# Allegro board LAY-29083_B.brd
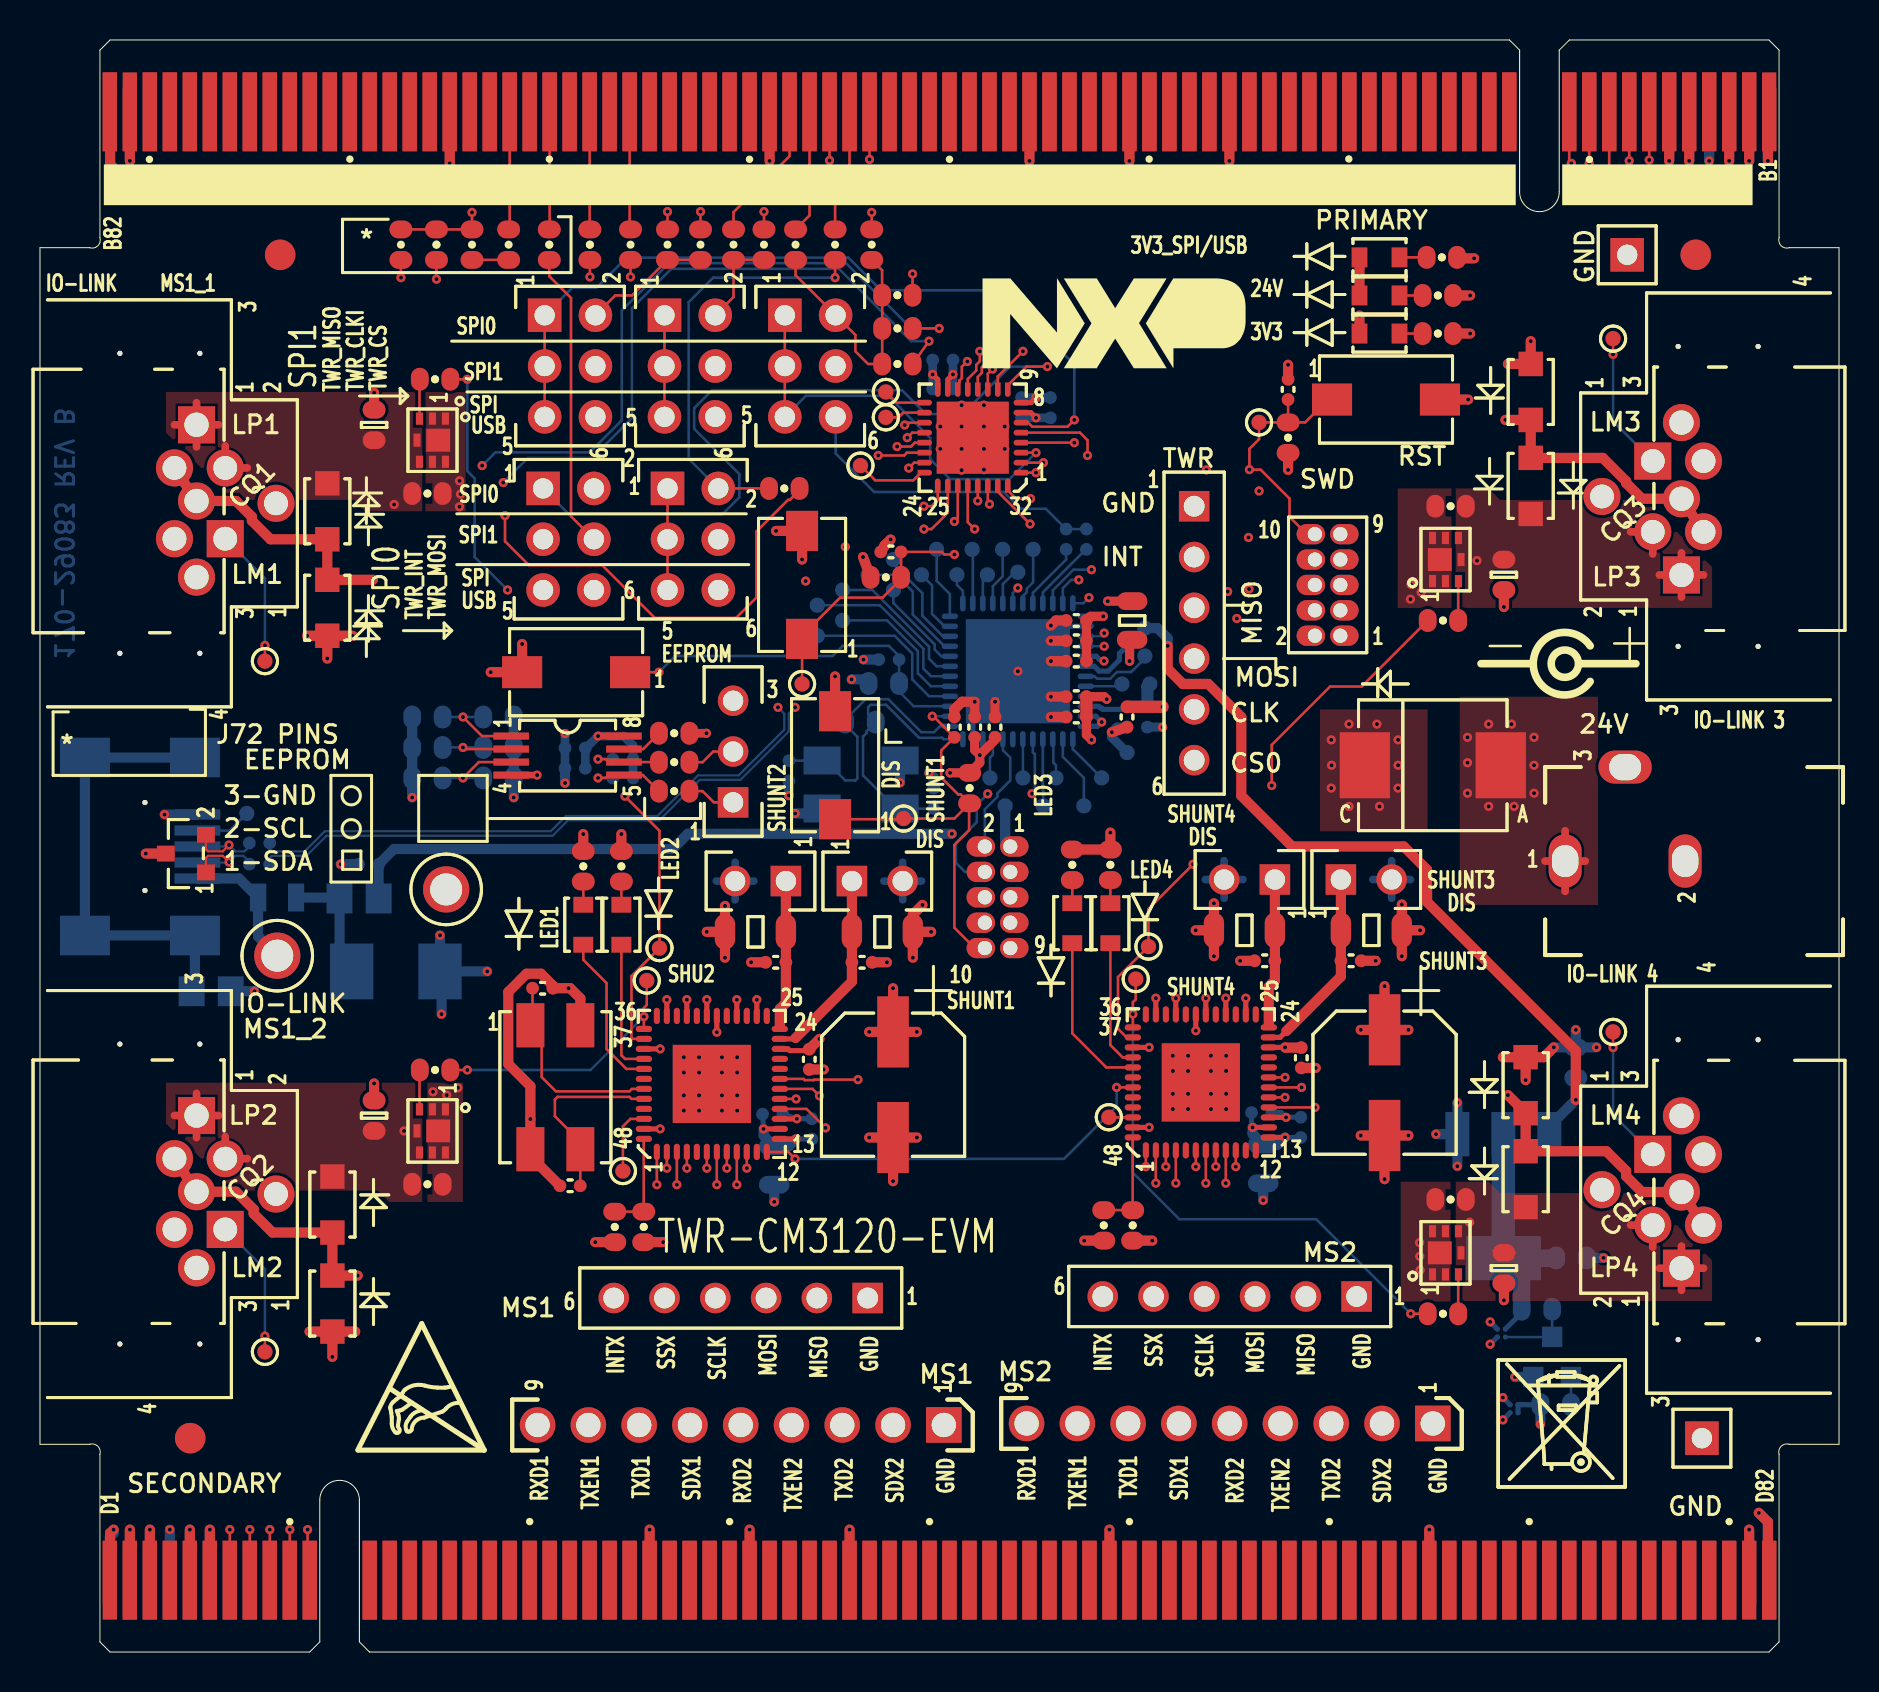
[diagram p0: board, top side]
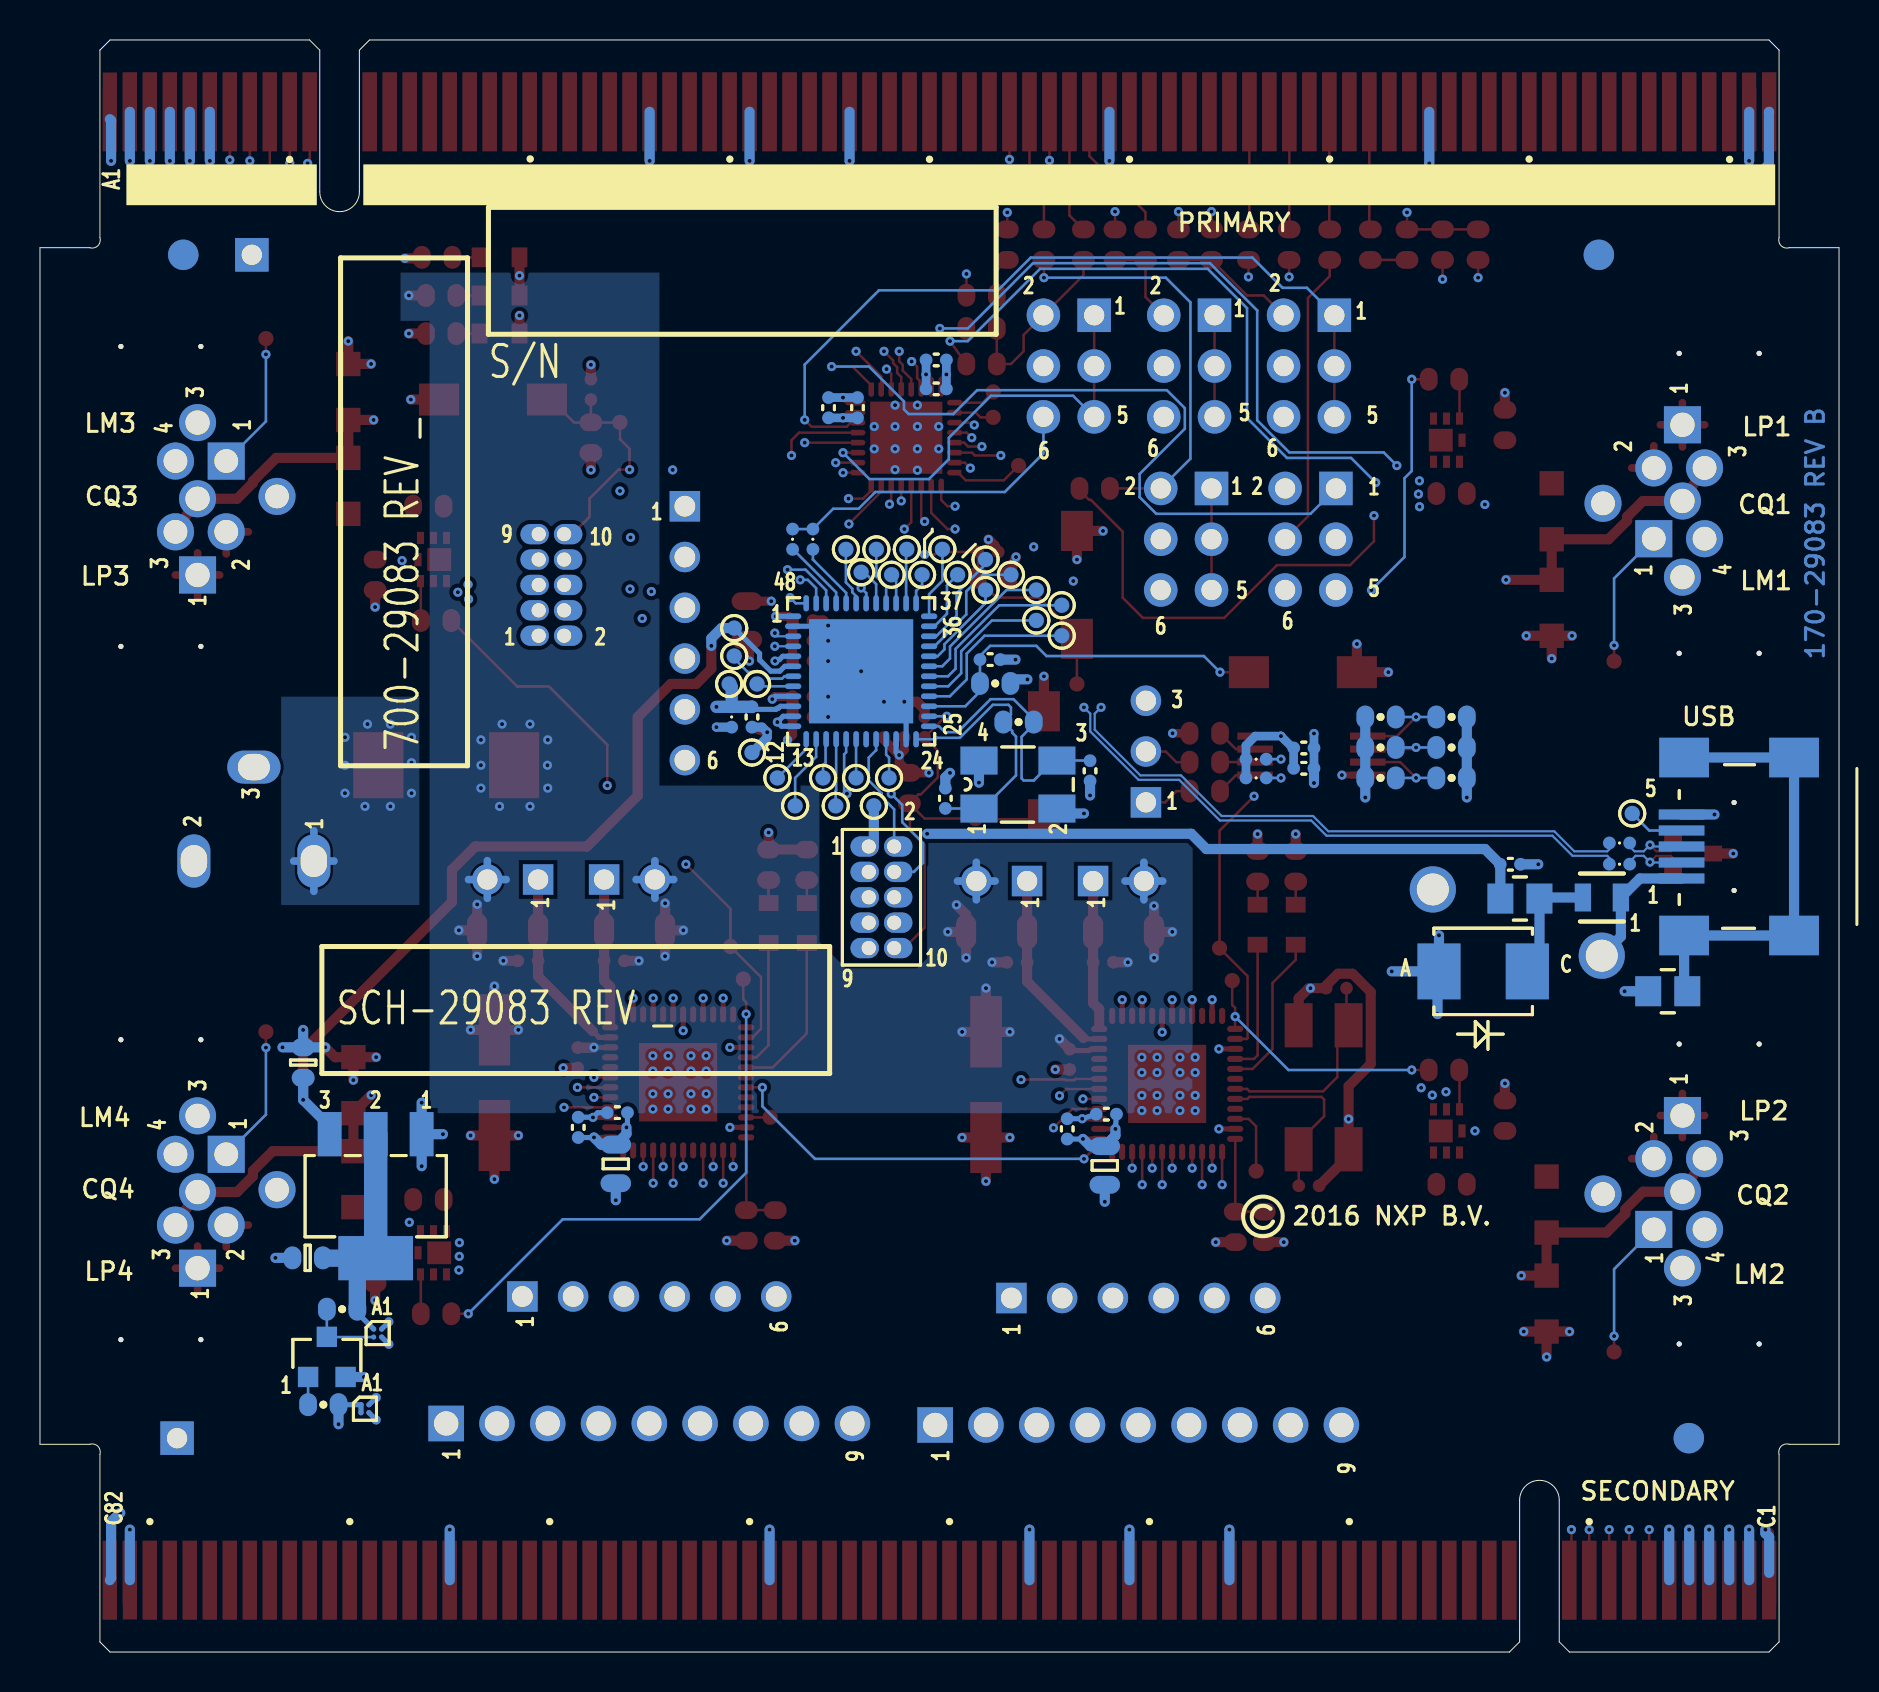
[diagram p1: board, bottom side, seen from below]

Outline 89.99 x 80.62 mm; copper layers: TOP, L2_PWR, L3_INT_1, L4_INT_2, L5_GND, BOTTOM. Coordinates in mm from the lower left corner of the outline.
Outline path: 0,70.23 0,10.39 2.49,10.39 arc(2.9,10.29) 3,9.88 3,0.51 3.51,0 13.49,0 14,0.51 14,7.59 arc(14.99,8.59) 15.98,7.59 15.98,0.51 16.48,0 86.49,0 86.99,0.51 86.99,9.88 arc(87.1,10.29) 87.5,10.39 89.99,10.39 89.99,70.23 87.5,70.23 arc(87.1,70.33) 86.99,70.74 86.99,80.11 86.49,80.62 76.5,80.62 76,80.11 76,73.03 arc(75.01,72.03) 74.02,73.03 74.02,80.11 73.51,80.62 3.51,80.62 3,80.11 3,70.74 arc(2.9,70.33) 2.49,70.23 0,70.23

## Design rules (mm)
net group USB_CONN_DN: nets USB_CONN_DN USB_DM
net group USB_CONN_DP: nets USB_CONN_DP USB_DP
net group POWER: nets 3V3_LDO 5V MS1_CQ1 MS1_CQ2 MS2_CQ1 MS2_CQ2 N52284736 P5V0_USB_CONN_VBUS P5V_USB SHIELD_K20USB VREFH

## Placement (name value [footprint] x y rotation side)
C5  0.1UF  [CC0402_25]  62.43 63.14 90 top
C6  4700PF  [CC0603_OV]  16.71 61.37 90 top
C7  0.1UF  [CC0402_25]  42.57 55.02 180 top
C8  4700PF  [CC0603_OV]  73.23 53.87 270 top
C9  1.0UF  [CC0402_25]  51.84 51.59 180 top
C10  2.2UF  [CC0805_OV]  54.63 51.59 90 top
C11  0.1UF  [CC0402_25]  51.84 50.57 180 top
C12  0.1UF  [CC0402_25]  51.84 49.56 180 top
C13  1.0UF  [CC0402_25]  51.84 47.78 180 top
C14  0.1UF  [CC0402_25]  51.84 46.76 180 top
C15  0.1UF  [CC0402_25]  54.38 46.76 90 top
C16  0.1UF  [CC0402_25]  45.74 46.25 90 top
C17  1.0UF  [CC0402_25]  46.76 46.25 90 top
C18  0.1UF  [CC0402_25]  47.77 46.25 90 top
C19  0.01UF  [CC0402_25]  61.26 34.57 0 top
C20  0.01UF  [CC0402_25]  65.58 34.57 180 top
C21  0.01UF  [CC0402_25]  36.8 34.49 0 top
C22  0.01UF  [CC0402_25]  41.12 34.49 180 top
C23  18PF  [CC0402_25]  25.15 33.2 0 top
C24  0.1uF  [CC0402_25]  63.09 29.72 270 top
C25  0.1uF  [CC0402_25]  38.48 29.64 270 top
C26  47UF  [CASE_D_AL]  67.26 28.47 270 top
C27  47UF  [CASE_D_AL]  42.67 28.37 270 top
C28  4700PF  [CC0603_OV]  16.71 26.82 90 top
C29  18PF  [CC0402_25]  26.52 23.32 180 top
C30  4700PF  [CC0603_OV]  73.23 19.2 270 top
C50  1.0UF  [CC0402_25]  45.16 64.62 180 bottom
C51  0.1UF  [CC0402_25]  45.16 63.17 180 bottom
C52  1.0UF  [CC0402_25]  50.55 62.23 90 bottom
C53  0.1UF  [CC0402_25]  49.1 62.23 90 bottom
C54  0.1UF  [CC0402_25]  42.46 49.63 180 bottom
C55  1.0UF  [CC0402_25]  54.38 46.76 270 bottom
C56  0.1UF  [CC0402_25]  26.77 45.21 180 bottom
C57  1.0UF  [CC0402_25]  26.77 44.2 180 bottom
C58  22PF  [CC0402_25]  37.47 44.07 270 bottom
C59  22PF  [CC0402_25]  44.7 42.7 90 bottom
C60  1.0UF  [CC0402_25]  16.44 39.4 180 bottom
C61  10uF  [CC0603_OV]  76.83 29.48 90 bottom
C65  0.1uF  [CC0402_25]  61.11 26.97 0 bottom
C66  0.1uF  [CC0402_25]  36.65 26.9 0 bottom
C67  0.1uF  [CC0402_25]  63.07 26.24 90 bottom
C68  0.1uF  [CC0402_25]  38.61 26.16 90 bottom
C70  10.0uF  [CC0805_OV]  61.19 24.41 270 bottom
C71  10.0uF  [CC0805_OV]  36.73 24.33 270 bottom
C75  10uF  [CC0603_OV]  76.6 19.71 0 bottom
D5  LED/GRN  [LED2_2P1X1P5_NSP]  67.01 69.75 0 top
D6  LED/GRN  [LED2_2P1X1P5_NSP]  67.01 67.84 0 top
D7  LED/GRN  [LED2_2P1X1P5_NSP]  67.01 65.94 0 top
D8  PTVS33VS1UR  [SOD123W]  74.57 63.02 90 top
D9  PTVS33VS1UR  [SOD123W]  74.57 58.32 90 top
D10  PTVS33VS1UR  [SOD123W]  14.37 57.05 270 top
D11  PTVS33VS1UR  [SOD123W]  14.37 52.22 270 top
D12  B560C-13-F  [SMC_CASE403]  69.67 44.35 0 top
D13  LED/GRN  [LED2_2P1X1P5_NSP]  51.64 36.45 90 top
D14  LED/GRN  [LED2_2P1X1P5_NSP]  53.54 36.45 90 top
D15  LED/GRN  [LED2_2P1X1P5_NSP]  27.18 36.37 90 top
D16  LED/GRN  [LED2_2P1X1P5_NSP]  29.08 36.37 90 top
D17  PTVS33VS1UR  [SOD123W]  74.32 28.35 90 top
D18  PTVS33VS1UR  [SOD123W]  74.32 23.65 90 top
D19  PTVS33VS1UR  [SOD123W]  14.63 22.38 270 top
D20  PTVS33VS1UR  [SOD123W]  14.63 17.43 270 top
D50  1SMB5919BT3G  [CASE403A_03]  17.8 34.04 0 bottom
F50  MFU0805FF00500P100  [FUSE_2X1P4]  11.86 37.73 0 bottom
J5  PCI EXPRESS TOWER SYSTEM  [CN2X82_FINGER_ASS]  3 14.76 0 top
J6  HDR 2X3  [HDR203]  25.24 66.85 0 top
J7  HDR 2X3  [HDR203]  31.24 66.85 0 top
J8  HDR 2X3  [HDR203]  37.26 66.85 0 top
J9  1436686  [CON5_TH_1436686]  80.67 59.56 90 top
J10  PLUG_1X3  [CON1X3_3P81_9P2X12P82]  82.11 53.87 90 top
J11  PLUG_1X3  [CON1X3_3P81_9P2X12P82]  7.83 61.37 270 top
J12  1436686  [CON5_TH_1436686]  9.27 55.68 270 top
J13  HDR 2X3  [HDR203]  25.17 58.19 0 top
J14  HDR 2X3  [HDR203]  31.39 58.19 0 top
J15  HDR 2X5  [HDR_5X2_FTSH_TH]  65.05 50.83 180 top
J16  HDR_1X3  [HDR103]  34.67 42.49 180 top
J17  CON_1_PWR  [PJ-102AH]  76.29 39.56 0 top
J18  HDR 1X2  [HDR102]  61.77 38.63 270 top
J19  HDR 1X2  [HDR102]  65.07 38.63 90 top
J20  HDR 1X2  [HDR102]  37.31 38.56 270 top
J21  HDR 1X2  [HDR102]  40.61 38.56 90 top
J22  1436686  [CON5_TH_1436686]  80.67 24.89 90 top
J23  PLUG_1X3  [CON1X3_3P81_9P2X12P82]  7.83 26.83 270 top
J24  PLUG_1X3  [CON1X3_3P81_9P2X12P82]  82.11 19.19 90 top
J25  1436686  [CON5_TH_1436686]  9.27 21.13 270 top
J52  CONN USB MINI-B  [CON5_USB_RA_SMT]  4.23 40.28 0 bottom
J53  HDR 2X5  [HDR_5X2_FTSH_TH]  48.54 40.29 180 bottom
JP5  HDR 1X1  [HDR101]  79.4 69.88 0 top
JP6  HDR 1X6  [HDR106_TH_TSW]  57.73 57.3 0 top
JP7  HDR 1X6  [HDR106_TH_TSW]  65.86 17.78 270 top
JP8  HDR 1X6  [HDR106_TH_TSW]  41.4 17.7 270 top
JP9  HDR 1X9  [HDR109]  69.67 11.43 270 top
JP10  HDR 1X9  [HDR109]  45.21 11.35 270 top
JP11  HDR 1X1  [HDR101]  83.13 10.69 0 top
L50  330 OHM  [IND_0805]  15.96 37.68 0 bottom
L51  330 OHM  [IND_0805]  8.57 33.05 0 bottom
NOREF  -  []  80.91 51.27 90 top
NOREF#2  -  []  19.63 24.98 90 top
NOREF#3  -  []  50.62 130.33 0 top
NOREF#4  -  []  3.51 0 90 top
NOREF#5  -  []  71.36 53.59 90 top
NOREF#6  -  []  18.98 24.98 0 top
NOREF#7  -  []  0 10.39 90 top
NOREF#8  -  []  69.26 55.69 0 top
NOREF#9  -  []  0 69.57 0 top
NOREF#10  -  []  -12.3 82.45 90 top
NOREF#11  -  []  70.02 19.96 90 top
NOREF#12  -  []  75.52 61.62 90 top
NOREF#13  -  []  69.66 21.04 0 top
NOREF#14  -  []  14.99 7.59 0 top
NOREF#15  -  []  6.73 59.22 90 top
NOREF#16  -  []  71.36 18.91 90 top
NOREF#17  -  []  80.54 47.79 90 top
NOREF#18  -  []  11.81 57.45 90 top
NOREF#19  -  []  4 49.95 90 top
NOREF#20  -  []  -9 52.9 90 top
NOREF#21  -  []  73.37 29.75 0 top
NOREF#22  -  [unnamed#2]  7.51 10.69 0 top
NOREF#23  -  []  13.42 50.82 90 top
NOREF#24  -  []  80.91 16.59 90 top
NOREF#25  -  []  -378.64 230.02 0 top
NOREF#26  -  []  13.42 55.65 0 top
NOREF#27  -  []  85.94 65.29 90 top
NOREF#28  -  []  77.24 28.12 90 top
NOREF#29  -  []  19.63 24.98 90 top
NOREF#30  -  []  18.86 60.6 0 top
NOREF#31  -  []  9.27 24.67 90 top
NOREF#32  -  []  82.11 19.19 90 top
NOREF#33  -  []  72.9 15.75 0 top
NOREF#34  -  []  8 15.4 90 top
NOREF#35  -  []  9.03 51.15 90 top
NOREF#36  -  []  81.94 50.29 90 top
NOREF#37  -  []  19.63 59.52 90 top
NOREF#38  -  []  8 49.95 90 top
NOREF#39  -  []  0 10.39 90 top
NOREF#40  -  []  9.27 55.68 90 top
NOREF#41  -  []  13.68 20.98 90 top
NOREF#42  -  []  19.63 59.52 90 top
NOREF#43  -  []  47.16 64.2 0 top
NOREF#44  -  []  80.54 67.79 90 top
NOREF#45  -  []  73.62 64.42 0 top
NOREF#46  -  []  73.34 11.77 0 top
NOREF#47  -  []  66.01 65.94 0 top
NOREF#48  -  []  66.01 67.84 0 top
NOREF#49  -  []  72.94 8.26 0 top
NOREF#50  -  []  70.02 54.64 90 top
NOREF#51  -  []  -4.3 -37.44 0 top
NOREF#52  -  []  2.22 15.54 0 top
NOREF#53  -  []  69.26 21.01 0 top
NOREF#54  -  []  18.58 25.01 0 top
NOREF#55  -  []  13.68 16.03 0 top
NOREF#56  -  []  71.08 19.96 90 top
NOREF#57  -  []  4 15.4 90 top
NOREF#58  -  []  89.74 11.12 90 top
NOREF#59  -  []  18.98 59.52 0 top
NOREF#60  -  []  73.62 59.72 0 top
NOREF#61  -  []  86.99 80.11 0 top
NOREF#62  -  []  8.33 27.97 0 top
NOREF#63  -  []  -9 32.9 90 top
NOREF#64  -  []  73.34 11.77 90 top
NOREF#65  -  []  73.37 25.05 0 top
NOREF#66  -  []  3 14.76 0 top
NOREF#67  -  []  70.96 18.88 90 top
NOREF#68  -  []  21.91 38.14 0 top
NOREF#69  -  []  89.74 11.12 90 top
NOREF#70  -  []  69.66 21.04 0 top
NOREF#71  -  []  203.02 -79.86 0 top
NOREF#72  -  []  -9 67.45 90 top
NOREF#73  -  []  89.74 45.79 90 top
NOREF#74  -  []  8 49.95 90 top
NOREF#75  -  []  82.11 53.87 90 top
NOREF#76  -  []  77.24 62.79 90 top
NOREF#77  -  []  18.58 25.01 90 top
NOREF#78  -  []  9.27 21.13 90 top
NOREF#79  -  []  29.08 35.37 90 top
NOREF#80  -  []  81.94 15.62 90 top
NOREF#81  -  [unnamed#2]  82.83 69.88 0 top
NOREF#82  -  []  7.83 57.56 90 top
NOREF#83  -  []  66.01 69.75 0 top
NOREF#84  -  []  89.74 11.12 90 top
NOREF#85  -  []  89.74 45.79 90 top
NOREF#86  -  []  75.01 88.58 0 top
NOREF#87  -  []  51.64 35.45 90 top
NOREF#88  -  []  70.96 53.56 90 top
NOREF#89  -  []  13.68 16.03 90 top
NOREF#90  -  []  69.66 55.71 0 top
NOREF#91  -  []  13.42 55.65 90 top
NOREF#92  -  []  70.96 18.88 0 top
NOREF#93  -  []  -9 87.45 90 top
NOREF#94  -  []  89.99 70.23 90 top
NOREF#95  -  []  51.81 -0.01 0 top
NOREF#96  -  []  89.99 11.05 90 top
NOREF#97  -  []  13.46 34.82 0 top
NOREF#98  -  []  75.27 22.25 90 top
NOREF#99  -  []  11.81 22.9 90 top
NOREF#100  -  []  81.94 30.62 90 top
NOREF#101  -  []  75.27 26.95 90 top
NOREF#102  -  []  77.24 28.12 90 top
NOREF#103  -  []  80.54 33.12 90 top
NOREF#104  -  []  80.54 13.12 90 top
NOREF#105  -  []  71.08 54.64 90 top
NOREF#106  -  []  8 15.4 90 top
NOREF#107  -  []  80.67 56.02 90 top
NOREF#108  -  []  3 0.51 0 top
NOREF#109  -  []  19.63 59.52 0 top
NOREF#110  -  []  -12.3 47.9 90 top
NOREF#111  -  []  -12.3 82.45 90 top
NOREF#112  -  []  15.92 10.1 0 top
NOREF#113  -  []  -12.3 47.9 90 top
NOREF#114  -  []  -93.52 -190.35 0 top
NOREF#115  -  []  9.03 16.61 90 top
NOREF#116  -  []  18.58 59.55 0 top
NOREF#117  -  []  77.24 18.12 90 top
NOREF#118  -  []  85.94 30.62 90 top
NOREF#119  -  []  3 14.76 0 top
NOREF#120  -  []  89.74 45.79 90 top
NOREF#121  -  []  13.42 50.82 0 top
NOREF#122  -  []  -88.44 146.2 0 top
NOREF#123  -  []  75.52 56.92 90 top
NOREF#124  -  []  -12.3 72.45 90 top
NOREF#125  -  []  69.66 55.71 0 top
NOREF#126  -  []  13.68 20.98 0 top
NOREF#127  -  []  6.73 24.67 90 top
NOREF#128  -  []  35.05 80.63 0 top
NOREF#129  -  []  73.54 11.97 90 top
NOREF#130  -  []  18.58 59.55 90 top
NOREF#131  -  []  19.63 24.98 0 top
NOREF#132  -  []  9.27 59.22 90 top
NOREF#133  -  []  89.99 10.39 90 top
NOREF#134  -  []  72.7 15.55 0 top
NOREF#135  -  []  18.98 24.98 90 top
NOREF#136  -  []  53.54 35.45 90 top
NOREF#137  -  []  70.96 53.56 0 top
NOREF#138  -  []  77.24 62.79 90 top
NOREF#139  -  []  18.98 59.52 90 top
NOREF#140  -  [unnamed#2]  12.01 69.88 0 top
NOREF#141  -  []  81.94 65.29 90 top
NOREF#142  -  []  0 10.39 90 top
NOREF#143  -  []  -409.17 -284.96 0 top
NOREF#144  -  []  77.24 52.79 90 top
NOREF#145  -  []  73.54 11.97 0 top
NOREF#146  -  []  18.86 26.06 0 top
NOREF#147  -  []  7.83 23.02 90 top
NOREF#148  -  []  27.18 35.37 90 top
NOREF#149  -  []  -12.3 37.9 90 top
NOREF#150  -  []  80.67 21.35 90 top
NOREF#151  -  []  141.19 79.22 0 top
NOREF#152  -  []  72.9 15.75 90 top
NOREF#153  -  []  72.7 15.55 90 top
NOREF#154  -  []  68.61 44.32 90 bottom
NOREF#155  -  []  30.88 22.38 180 bottom
NOREF#156  -  [unnamed#2]  7.51 10.69 180 bottom
NOREF#157  -  []  28.82 21.76 180 bottom
NOREF#158  -  []  42.16 72.25 0 bottom
NOREF#159  -  [unnamed#2]  82.83 69.88 180 bottom
NOREF#160  -  [unnamed#2]  12.01 69.88 180 bottom
NOREF#161  -  []  75.89 28.93 180 bottom
Q5  PMPB85ENEAX  [SOT1220]  19.63 60.6 270 top
Q6  PMPB85ENEAX  [SOT1220]  70.31 54.64 90 top
Q7  PMPB85ENEAX  [SOT1220]  19.63 26.06 270 top
Q8  PMPB85ENEAX  [SOT1220]  70.31 19.96 90 top
Q50  BC847C  [SOT23-40X40]  75.64 14.76 180 bottom
R5  0  [RC0603_OV]  18.06 70.38 270 top
R6  0  [RC0603_OV]  19.83 70.38 270 top
R7  0  [RC0603_OV]  21.61 70.38 270 top
R8  0  [RC0603_OV]  23.44 70.38 90 top
R9  0  [RC0603_OV]  25.48 70.38 90 top
R10  0  [RC0603_OV]  27.51 70.38 90 top
R11  0  [RC0603_OV]  29.54 70.38 90 top
R12  0  [RC0603_OV]  31.39 70.38 90 top
R13  0  [RC0603_OV]  33.04 70.38 90 top
R14  0  [RC0603_OV]  34.69 70.38 90 top
R15  0  [RC0603_OV]  36.22 70.38 90 top
R16  0  [RC0603_OV]  37.8 70.38 90 top
R17  0  [RC0603_OV]  39.77 70.38 90 top
R18  0  [RC0603_OV]  41.61 70.38 90 top
R19  560  [RC0603_OV]  70.13 69.75 0 top
R20  0  [RC0603_OV]  42.89 67.86 0 top
R21  3.83K  [RC0603_OV]  69.93 67.84 180 top
R22  0  [RC0603_OV]  42.89 66.19 0 top
R23  560  [RC0603_OV]  69.93 65.94 0 top
R24  0  [RC0603_OV]  42.89 64.42 0 top
R25  0  [RC0603_OV]  19.76 63.65 0 top
R26  10K  [RC0603_OV]  62.43 60.73 90 top
R27  0  [RC0603_OV]  37.23 58.19 0 top
R28  0  [RC0603_OV]  19.38 57.94 0 top
R29  0  [RC0603_OV]  70.56 57.3 180 top
R30  10K  [RC0603_OV]  42.31 53.75 0 top
R31  0  [RC0603_OV]  70.18 51.59 180 top
R32  0  [RC0603_OV]  31.72 45.95 0 top
R33  0  [RC0603_OV]  31.72 44.5 0 top
R34  10K  [RC0603_OV]  46.5 43.21 270 top
R35  0  [RC0603_OV]  31.72 43.05 0 top
R36  560  [RC0603_OV]  51.64 39.37 90 top
R37  560  [RC0603_OV]  53.54 39.37 90 top
R38  560  [RC0603_OV]  27.18 39.29 90 top
R39  560  [RC0603_OV]  29.08 39.29 90 top
R40  0.5  [RC1206_OV]  60.25 36.09 0 top
R41  0.5  [RC1206_OV]  66.6 36.09 180 top
R42  0.5  [RC1206_OV]  35.79 36.02 0 top
R43  0.5  [RC1206_OV]  42.14 36.02 180 top
R44  0  [RC0603_OV]  19.76 29.11 0 top
R45  0  [RC0603_OV]  19.38 23.39 0 top
R46  0  [RC0603_OV]  70.56 22.63 180 top
R47  0  [RC0603_OV]  53.21 21.34 90 top
R48  0  [RC0603_OV]  54.66 21.34 270 top
R49  0  [RC0603_OV]  28.75 21.26 90 top
R50  0  [RC0402_25]  52.35 55.65 90 bottom
R51  0  [RC0402_25]  51.33 55.65 90 bottom
R52  10K  [RC0603_OV]  42.21 48.44 0 bottom
R53  0  [RC0402_25]  55.39 46.76 270 bottom
R54  2.2K  [RC0603_OV]  22.94 46.76 0 bottom
R55  2.2K  [RC0603_OV]  19.38 46.76 0 bottom
R56  1.0M  [RC0603_OV]  41.04 46.51 180 bottom
R57  2.2K  [RC0603_OV]  22.94 45.24 0 bottom
R58  2.2K  [RC0603_OV]  19.38 45.24 0 bottom
R59  2.2K  [RC0402_25]  29.16 44.65 180 bottom
R60  2.2K  [RC0402_25]  29.16 43.71 180 bottom
R61  2.2K  [RC0603_OV]  22.94 43.71 0 bottom
R62  2.2K  [RC0603_OV]  19.38 43.71 0 bottom
R63  33  [RC0402_25]  10.98 40.46 0 bottom
R64  33  [RC0402_25]  10.98 39.4 0 bottom
R65  3.3K  [RC0603_OV]  74.88 17.14 0 bottom
R66  33.0K  [RC0603_OV]  75.82 12.37 0 bottom
R67  0  [RC0603_OV]  30.2 21.26 270 top
R68  0  [RC0603_OV]  70.18 16.92 180 top
SW5  EVQ-PE105K  [SW2_SPST_3P5X6P0_5P0]  67.33 62.64 270 top
SW6  EVQ-PE105K  [SW2_SPST_3P5X6P0_5P0]  38.12 53.37 0 top
SW7  EVQ-PE105K  [SW2_SPST_3P5X6P0_5P0]  26.82 49 90 top
SW8  EVQ-PE105K  [SW2_SPST_3P5X6P0_5P0]  39.77 44.35 0 top
TP5  -  [TPAD_030]  78.69 65.68 90 top
TP6  -  [TPAD_030]  42.31 63.02 0 top
TP7  -  [TPAD_030]  42.31 61.75 0 top
TP8  -  [TPAD_030]  60.98 61.49 180 top
TP9  -  [TPAD_030]  41.04 59.34 0 top
TP10  -  [TPAD_030]  11.25 49.56 270 top
TP11  -  [TPAD_030]  38.12 48.41 0 top
TP12  -  [TPAD_030]  43.2 41.68 0 top
TP13  TESTLOOP_BLACK  [TP_TH_063]  20.32 38.14 0 top
TP14  -  [TPAD_030]  55.45 35.28 90 top
TP15  -  [TPAD_030]  30.99 35.2 90 top
TP16  TESTLOOP_RED  [TP_TH_063]  11.87 34.82 0 top
TP17  -  [TPAD_030]  54.81 33.66 90 top
TP18  -  [TPAD_030]  30.35 33.58 90 top
TP19  -  [TPAD_030]  78.69 31.01 90 top
TP20  -  [TPAD_030]  53.47 26.75 90 top
TP21  -  [TPAD_030]  29.16 24.05 90 top
TP22  -  [TPAD_030]  11.25 15.01 270 top
TP57  -  [TPAD_030]  49.68 55.14 180 bottom
TP58  -  [TPAD_030]  48.15 55.14 180 bottom
TP64  -  [TPAD_030]  46.63 55.14 180 bottom
TP66  -  [TPAD_030]  44.85 55.14 180 bottom
TP67  -  [TPAD_030]  42.69 54.64 180 bottom
TP68  -  [TPAD_030]  48.92 54 180 bottom
TP69  -  [TPAD_030]  47.39 53.87 180 bottom
TP70  -  [TPAD_030]  45.87 53.87 180 bottom
TP71  -  [TPAD_030]  44.09 53.87 180 bottom
TP72  -  [TPAD_030]  41.42 53.87 180 bottom
TP73  -  [TPAD_030]  42.69 53.11 180 bottom
TP74  -  [TPAD_030]  40.15 53.11 180 bottom
TP75  -  [TPAD_030]  38.88 52.35 180 bottom
TP76  -  [TPAD_030]  40.15 51.59 180 bottom
TP77  -  [TPAD_030]  55.27 51.21 180 bottom
TP78  -  [TPAD_030]  38.88 50.83 180 bottom
TP79  -  [TPAD_030]  55.27 49.81 180 bottom
TP80  -  [TPAD_030]  55.52 48.41 180 bottom
TP81  -  [TPAD_030]  54.12 48.41 180 bottom
TP82  -  [TPAD_030]  54.38 44.98 180 bottom
TP83  -  [TPAD_030]  53.11 43.71 180 bottom
TP84  -  [TPAD_030]  50.82 43.71 180 bottom
TP85  -  [TPAD_030]  49.17 43.71 180 bottom
TP86  -  [TPAD_030]  47.52 43.71 180 bottom
TP87  -  [TPAD_030]  52.22 42.32 180 bottom
TP88  -  [TPAD_030]  50.19 42.32 180 bottom
TP89  -  [TPAD_030]  48.28 42.32 180 bottom
TP90  -  [TPAD_030]  10.34 41.94 180 bottom
U5  MKL17Z64VFM4  [QFN32_S142EP]  46.66 60.73 180 top
U6  24FC256  [TSSOP8]  26.39 44.83 0 top
U7  GSOT05C-GS08  [SOT23_A]  7.3 39.93 90 top
U8  MC34CM3120EP  [QFN48_0P5_7X7_EP3P9_NSP]  58.07 28.49 90 top
U9  MC34CM3120EP  [QFN48_0P5_7X7_EP3P9_NSP]  33.61 28.41 90 top
U50  MKL25Z128VFT4  [QFN_48_0P5_7X7]  48.92 49.05 180 bottom
U51  NCP1117ST33T3G  [SOT223]  73.2 22.8 0 bottom
U52  NX3P190UK  [WLCSP4_0P4_0P8X0P8_SMDP]  73.1 15.95 180 bottom
U53  NX3P190UK  [WLCSP4_0P4_0P8X0P8_SMDP]  73.74 12.17 180 bottom
Y5  14.7456MHZ  [XTAL_4_7X5]  25.78 28.24 270 top
Y50  8MHZ  [XTLOSC4_5X3MM_SM]  41.07 43.38 180 bottom

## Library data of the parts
C5-C9 C11-C25 C28-C30 C50-C61 C65-C68 C70 C71 C75 = CAP_NP
C10 = CAP_NP: tolerance: 10%
C26 C27 = CAP_POL
D5-D7 D13-D16 = LED
D8-D11 D17-D20 = DIODE_TVS
D12 = DIODE_SCHTKY
D50 = ZDIODE
F50 = FUSE
J5 = CONN_PCI_XPRESS_X16_328P
J6-J8 J13 J14 = CONN_HDR_3X2
J9 J12 J22 J25 = CON5_DIN
J10 J11 J16 J23 J24 = CONN_HDR_3X1
J15 J53 = CONN_HDR_5X2
J17 = DC POWER JACK
J18-J21 = CONN_HDR_2X1
J52 = USB_MINI_AB_RECEPTACLE
JP5 JP11 = CONN_HDR_1X1
JP6-JP8 = CONN_HDR_6X1
JP9 JP10 = CONN_HDR_9X1
L50 L51 = BEAD: tolerance: 25%
Q5-Q8 = PMPB85ENEA_SOT1220_8P
Q50 = NPN
R5-R18 R20-R22 R24-R35 R40-R62 R65-R68 = RES
R19 R23 R36-R39 = RES: tolerance: 5%
R63 R64 = RES: signal model: RES_RC0402_25_DISCRETE_0.4MM__1_33
SW5-SW8 = SW2P
TP5-TP12 TP14 TP15 TP17-TP22 TP57 TP58 TP64 TP66-TP90 = TESTLOOP
TP13 TP16 = TestLoop
U5 = KL17Z64VF_QFN_32P_EP
U6 = Atmel_Serial_EEPROM_64K-1
U7 = DIODE_2LINE_ESD
U8 U9 = MC34CM3120_48P
U50 = MKL25Z128VFT4_49P
U51 = LD1117AS18
U52 U53 = ADP172_CSP_4P
Y5 = XTAL_13Y
Y50 = CRYSTAL_JXS63

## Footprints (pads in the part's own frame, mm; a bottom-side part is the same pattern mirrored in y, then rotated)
CASE403A_03
  rect 2.159x2.794 smd: A(2.21,0) C(-2.21,0)
CASE_D_AL
  rect 3.556x1.575 smd: 1(-2.642,0) 2(2.642,0)
CC0402_25
  round 0.635 smd: 1(-0.508,0) 2(0.508,0)
CC0603_OV
  oval 0.889x1.143 smd: 1(-0.762,0) 2(0.762,0)
CC0805_OV
  oval 0.889x1.524 smd: 1(-0.965,0) 2(0.965,0)
CN2X82_FINGER_ASS
  rect 0.711x3.2 smd: A1(83.499,61.9) B81(1.499,61.9) C1(0.499,-10.795) D81(82.499,-10.795)
  rect 0.711x3.937 smd: A2(82.499,62.268) A3(81.499,62.268) A4(80.499,62.268) A5(79.499,62.268) A6(78.499,62.268) A7(77.499,62.268) A8(76.499,62.268) A9(75.499,62.268) A10(74.499,62.268) A11(73.499,62.268) A12(70.499,62.268) A13(69.499,62.268) A14(68.499,62.268) A15(67.499,62.268) A16(66.499,62.268) A17(65.499,62.268) A18(64.499,62.268) A19(63.499,62.268) A20(62.499,62.268) A21(61.499,62.268) A22(60.499,62.268) A23(59.499,62.268) A24(58.499,62.268) A25(57.499,62.268) A26(56.499,62.268) A27(55.499,62.268) A28(54.499,62.268) A29(53.499,62.268) A30(52.499,62.268) A31(51.499,62.268) A32(50.499,62.268) A33(49.499,62.268) A34(48.499,62.268) A35(47.499,62.268) A36(46.499,62.268) A37(45.499,62.268) A38(44.499,62.268) A39(43.499,62.268) A40(42.499,62.268) A41(41.499,62.268) A42(40.499,62.268) A43(39.499,62.268) A44(38.499,62.268) A45(37.499,62.268) A46(36.499,62.268) A47(35.499,62.268) A48(34.499,62.268) A49(33.499,62.268) A50(32.499,62.268) A51(31.499,62.268) A52(30.499,62.268) A53(29.499,62.268) A54(28.499,62.268) A55(27.499,62.268) A56(26.499,62.268) A57(25.499,62.268) A58(24.499,62.268) A59(23.499,62.268) A60(22.499,62.268) A61(21.499,62.268) A62(20.499,62.268) A63(19.499,62.268) A64(18.499,62.268) A65(17.499,62.268) A66(16.499,62.268) A67(15.499,62.268) A68(14.499,62.268) A69(13.499,62.268) A70(12.499,62.268) A71(11.499,62.268) A72(10.499,62.268) A73(9.499,62.268) A74(8.499,62.268) A75(7.499,62.268) A76(6.499,62.268) A77(5.499,62.268) A78(4.499,62.268) A79(3.499,62.268) A80(2.499,62.268) A81(1.499,62.268) A82(0.499,62.268) B1(83.499,62.268) B2(82.499,62.268) B3(81.499,62.268) B4(80.499,62.268) B5(79.499,62.268) B6(78.499,62.268) B7(77.499,62.268) B8(76.499,62.268) B9(75.499,62.268) B10(74.499,62.268) B11(73.499,62.268) B12(70.499,62.268) B13(69.499,62.268) B14(68.499,62.268) B15(67.499,62.268) B16(66.499,62.268) B17(65.499,62.268) B18(64.499,62.268) B19(63.499,62.268) B20(62.499,62.268) B21(61.499,62.268) B22(60.499,62.268) B23(59.499,62.268) B24(58.499,62.268) B25(57.499,62.268) B26(56.499,62.268) B27(55.499,62.268) B28(54.499,62.268) B29(53.499,62.268) B30(52.499,62.268) B31(51.499,62.268) B32(50.499,62.268) B33(49.499,62.268) B34(48.499,62.268) B35(47.499,62.268) B36(46.499,62.268) B37(45.499,62.268) B38(44.499,62.268) B39(43.499,62.268) B40(42.499,62.268) B41(41.499,62.268) B42(40.499,62.268) B43(39.499,62.268) B44(38.499,62.268) B45(37.499,62.268) B46(36.499,62.268) B47(35.499,62.268) B48(34.499,62.268) B49(33.499,62.268) B50(32.499,62.268) B51(31.499,62.268) B52(30.499,62.268) B53(29.499,62.268) B54(28.499,62.268) B55(27.499,62.268) B56(26.499,62.268) B57(25.499,62.268) B58(24.499,62.268) B59(23.499,62.268) B60(22.499,62.268) B61(21.499,62.268) B62(20.499,62.268) B63(19.499,62.268) B64(18.499,62.268) B65(17.499,62.268) B66(16.499,62.268) B67(15.499,62.268) B68(14.499,62.268) B69(13.499,62.268) B70(12.499,62.268) B71(11.499,62.268) B72(10.499,62.268) B73(9.499,62.268) B74(8.499,62.268) B75(7.499,62.268) B76(6.499,62.268) B77(5.499,62.268) B78(4.499,62.268) B79(3.499,62.268) B80(2.499,62.268) B82(0.499,62.268) C2(1.499,-11.163) C3(2.499,-11.163) C4(3.499,-11.163) C5(4.499,-11.163) C6(5.499,-11.163) C7(6.499,-11.163) C8(7.499,-11.163) C9(8.499,-11.163) C10(9.499,-11.163) C11(10.499,-11.163) C12(13.499,-11.163) C13(14.499,-11.163) C14(15.499,-11.163) C15(16.499,-11.163) C16(17.499,-11.163) C17(18.499,-11.163) C18(19.499,-11.163) C19(20.499,-11.163) C20(21.499,-11.163) C21(22.499,-11.163) C22(23.499,-11.163) C23(24.499,-11.163) C24(25.499,-11.163) C25(26.499,-11.163) C26(27.499,-11.163) C27(28.499,-11.163) C28(29.499,-11.163) C29(30.499,-11.163) C30(31.499,-11.163) C31(32.499,-11.163) C32(33.499,-11.163) C33(34.499,-11.163) C34(35.499,-11.163) C35(36.499,-11.163) C36(37.499,-11.163) C37(38.499,-11.163) C38(39.499,-11.163) C39(40.499,-11.163) C40(41.499,-11.163) C41(42.499,-11.163) C42(43.499,-11.163) C43(44.499,-11.163) C44(45.499,-11.163) C45(46.499,-11.163) C46(47.499,-11.163) C47(48.499,-11.163) C48(49.499,-11.163) C49(50.499,-11.163) C50(51.499,-11.163) C51(52.499,-11.163) C52(53.499,-11.163) C53(54.499,-11.163) C54(55.499,-11.163) C55(56.499,-11.163) C56(57.499,-11.163) C57(58.499,-11.163) C58(59.499,-11.163) C59(60.499,-11.163) C60(61.499,-11.163) C61(62.499,-11.163) C62(63.499,-11.163) C63(64.499,-11.163) C64(65.499,-11.163) C65(66.499,-11.163) C66(67.499,-11.163) C67(68.499,-11.163) C68(69.499,-11.163) C69(70.499,-11.163) C70(71.499,-11.163) C71(72.499,-11.163) C72(73.499,-11.163) C73(74.499,-11.163) C74(75.499,-11.163) C75(76.499,-11.163) C76(77.499,-11.163) C77(78.499,-11.163) C78(79.499,-11.163) C79(80.499,-11.163) C80(81.499,-11.163) C81(82.499,-11.163) C82(83.499,-11.163) D1(0.499,-11.163) D2(1.499,-11.163) D3(2.499,-11.163) D4(3.499,-11.163) D5(4.499,-11.163) D6(5.499,-11.163) D7(6.499,-11.163) D8(7.499,-11.163) D9(8.499,-11.163) D10(9.499,-11.163) D11(10.499,-11.163) D12(13.499,-11.163) D13(14.499,-11.163) D14(15.499,-11.163) D15(16.499,-11.163) D16(17.499,-11.163) D17(18.499,-11.163) D18(19.499,-11.163) D19(20.499,-11.163) D20(21.499,-11.163) D21(22.499,-11.163) D22(23.499,-11.163) D23(24.499,-11.163) D24(25.499,-11.163) D25(26.499,-11.163) D26(27.499,-11.163) D27(28.499,-11.163) D28(29.499,-11.163) D29(30.499,-11.163) D30(31.499,-11.163) D31(32.499,-11.163) D32(33.499,-11.163) D33(34.499,-11.163) D34(35.499,-11.163) D35(36.499,-11.163) D36(37.499,-11.163) D37(38.499,-11.163) D38(39.499,-11.163) D39(40.499,-11.163) D40(41.499,-11.163) D41(42.499,-11.163) D42(43.499,-11.163) D43(44.499,-11.163) D44(45.499,-11.163) D45(46.499,-11.163) D46(47.499,-11.163) D47(48.499,-11.163) D48(49.499,-11.163) D49(50.499,-11.163) D50(51.499,-11.163) D51(52.499,-11.163) D52(53.499,-11.163) D53(54.499,-11.163) D54(55.499,-11.163) D55(56.499,-11.163) D56(57.499,-11.163) D57(58.499,-11.163) D58(59.499,-11.163) D59(60.499,-11.163) D60(61.499,-11.163) D61(62.499,-11.163) D62(63.499,-11.163) D63(64.499,-11.163) D64(65.499,-11.163) D65(66.499,-11.163) D66(67.499,-11.163) D67(68.499,-11.163) D68(69.499,-11.163) D69(70.499,-11.163) D70(71.499,-11.163) D71(72.499,-11.163) D72(73.499,-11.163) D73(74.499,-11.163) D74(75.499,-11.163) D75(76.499,-11.163) D76(77.499,-11.163) D77(78.499,-11.163) D78(79.499,-11.163) D79(80.499,-11.163) D80(81.499,-11.163) D82(83.499,-11.163)
CON1X3_3P81_9P2X12P82
  rect 1.854x1.854 hole 1.219: 1(0,0)
  round 1.854 hole 1.219: 2(3.81,0) 3(7.62,0)
CON5_TH_1436686
  round 0.254 hole 2.057 unplated: (-9.27,-1.27) (5.73,-1.27)
  round 0.254 hole 2.794 unplated: (-9.27,-5.27) (5.73,-5.27)
  rect 1.854x1.854 hole 1.194: 1(0,0)
  round 1.854 hole 1.194: 2(-3.54,0) 3(-3.54,-2.54) 4(0,-2.54) 5(-1.77,2.54)
CON5_USB_RA_SMT
  round 0.254 hole 0.889 unplated: (1.025,-2.2) (1.025,2.2)
  rect 2.286x0.508 smd: 1(3.65,1.6) 2(3.65,0.8) 3(3.65,0) 4(3.65,-0.8) 5(3.65,-1.6)
  rect 2.489x1.981 smd: S1(3.525,4.45) S2(3.525,-4.45) S3(-1.975,4.45) S4(-1.975,-4.45)
FUSE_2X1P4
  rect 0.813x1.397 smd: 1(-0.95,0) 2(0.95,0)
HDR101
  rect 1.676x1.676 hole 1.016: 1(0,0)
HDR102
  rect 1.524x1.524 hole 1.016: 1(0,0)
  round 1.524 hole 1.016: 2(0,-2.54)
HDR103
  rect 1.524x1.524 hole 1.016: 1(0,0)
  round 1.524 hole 1.016: 2(0,-2.54) 3(0,-5.08)
HDR106_TH_TSW
  rect 1.524x1.524 hole 1.041: 1(0,0)
  round 1.524 hole 1.041: 2(0,-2.54) 3(0,-5.08) 4(0,-7.62) 5(0,-10.16) 6(0,-12.7)
HDR109
  rect 1.778x1.778 hole 1.219: 1(0,0)
  round 1.778 hole 1.219: 2(0,-2.54) 3(0,-5.08) 4(0,-7.62) 5(0,-10.16) 6(0,-12.7) 7(0,-15.24) 8(0,-17.78) 9(0,-20.32)
HDR203
  rect 1.676x1.676 hole 1.016: 1(0,0)
  round 1.676 hole 1.016: 2(2.54,0) 3(0,-2.54) 4(2.54,-2.54) 5(0,-5.08) 6(2.54,-5.08)
HDR_5X2_FTSH_TH
  oval 1.422x1.016 hole 0.711: 1(0,0) 2(1.27,0) 3(0,-1.27) 4(1.27,-1.27) 5(0,-2.54) 6(1.27,-2.54) 7(0,-3.81) 8(1.27,-3.81) 9(0,-5.08) 10(1.27,-5.08)
IND_0805
  rect 1.295x1.499 smd: 1(-0.978,0) 2(0.978,0)
LED2_2P1X1P5_NSP
  rect 0.787x0.991 smd: A(1,0) C(-1,0)
PJ-102AH
  oval 1.651x2.667 hole 1.321x1.6: 1(0,0) 2(6,0)
  oval 2.667x1.651 hole 1.6x1.321: 3(3,4.7)
QFN32_S142EP
  custom 0.07x0.07 smd: 1(-2.4,1.751) 2(-2.4,1.251) 3(-2.4,0.751) 4(-2.4,0.25) 5(-2.4,-0.25) 6(-2.4,-0.751) 7(-2.4,-1.251) 8(-2.4,-1.751) 9(-1.751,-2.4) 10(-1.251,-2.4) 11(-0.751,-2.4) 12(-0.25,-2.4) 13(0.25,-2.4) 14(0.751,-2.4) 15(1.251,-2.4) 16(1.751,-2.4) 17(2.4,-1.751) 18(2.4,-1.251) 19(2.4,-0.751) 20(2.4,-0.25) 21(2.4,0.25) 22(2.4,0.751) 23(2.4,1.251) 24(2.4,1.751) 25(1.751,2.4) 26(1.251,2.4) 27(0.751,2.4) 28(0.25,2.4) 29(-0.25,2.4) 30(-0.751,2.4) 31(-1.251,2.4) 32(-1.751,2.4)
  rect 3.607x3.607 smd: 33(0,0)
QFN48_0P5_7X7_EP3P9_NSP
  oval 0.813x0.305 smd: 1(-3.4,2.75) 2(-3.4,2.25) 3(-3.4,1.75) 4(-3.4,1.25) 5(-3.4,0.75) 6(-3.4,0.25) 7(-3.4,-0.25) 8(-3.4,-0.75) 9(-3.4,-1.25) 10(-3.4,-1.75) 11(-3.4,-2.25) 12(-3.4,-2.75) 25(3.4,-2.75) 26(3.4,-2.25) 27(3.4,-1.75) 28(3.4,-1.25) 29(3.4,-0.75) 30(3.4,-0.25) 31(3.4,0.25) 32(3.4,0.75) 33(3.4,1.25) 34(3.4,1.75) 35(3.4,2.25) 36(3.4,2.75)
  oval 0.305x0.813 smd: 13(-2.75,-3.4) 14(-2.25,-3.4) 15(-1.75,-3.4) 16(-1.25,-3.4) 17(-0.75,-3.4) 18(-0.25,-3.4) 19(0.25,-3.4) 20(0.75,-3.4) 21(1.25,-3.4) 22(1.75,-3.4) 23(2.25,-3.4) 24(2.75,-3.4) 37(2.75,3.4) 38(2.25,3.4) 39(1.75,3.4) 40(1.25,3.4) 41(0.75,3.4) 42(0.25,3.4) 43(-0.25,3.4) 44(-0.75,3.4) 45(-1.25,3.4) 46(-1.75,3.4) 47(-2.25,3.4) 48(-2.75,3.4)
  rect 3.912x3.912 smd: 49(0,0)
QFN_48_0P5_7X7
  oval 0.813x0.279 smd: 1(-3.4,2.75) 2(-3.4,2.25) 3(-3.4,1.75) 4(-3.4,1.25) 5(-3.4,0.75) 6(-3.4,0.25) 7(-3.4,-0.25) 8(-3.4,-0.75) 9(-3.4,-1.25) 10(-3.4,-1.75) 11(-3.4,-2.25) 12(-3.4,-2.75) 25(3.4,-2.75) 26(3.4,-2.25) 27(3.4,-1.75) 28(3.4,-1.25) 29(3.4,-0.75) 30(3.4,-0.25) 31(3.4,0.25) 32(3.4,0.75) 33(3.4,1.25) 34(3.4,1.75) 35(3.4,2.25) 36(3.4,2.75)
  oval 0.279x0.813 smd: 13(-2.75,-3.4) 14(-2.25,-3.4) 15(-1.75,-3.4) 16(-1.25,-3.4) 17(-0.75,-3.4) 18(-0.25,-3.4) 19(0.25,-3.4) 20(0.75,-3.4) 21(1.25,-3.4) 22(1.75,-3.4) 23(2.25,-3.4) 24(2.75,-3.4) 37(2.75,3.4) 38(2.25,3.4) 39(1.75,3.4) 40(1.25,3.4) 41(0.75,3.4) 42(0.25,3.4) 43(-0.25,3.4) 44(-0.75,3.4) 45(-1.25,3.4) 46(-1.75,3.4) 47(-2.25,3.4) 48(-2.75,3.4)
  rect 5.207x5.207 smd: 49(0,0)
RC0402_25
  round 0.635 smd: 1(-0.508,0) 2(0.508,0)
RC0603_OV
  oval 0.889x1.143 smd: 1(-0.762,0) 2(0.762,0)
RC1206_OV
  oval 1.016x1.778 smd: 1(-1.524,0) 2(1.524,0)
SMC_CASE403
  rect 2.515x3.302 smd: A(3.4,0) C(-3.4,0)
SOD123W
  rect 1.219x1.219 smd: A(1.4,0) C(-1.4,0)
SOT23-40X40
  rect 1.016x1.016 smd: 1(-0.94,-1.003) 2(0.94,-1.003) 3(0,1.003)
SOT23_A
  rect 0.787x0.889 smd: 1(-0.94,-1.003) 2(0.94,-1.003) 3(0,1.003)
SOT223
  rect 1.194x2.21 smd: 1(-2.3,-3.1) 2(0,-3.1) 3(2.3,-3.1)
  rect 3.734x2.21 smd: 4(0,3.1)
SOT1220
  rect 0.61x0.356 smd: 1(-1.079,0.65) 2(-1.079,0) 3(-1.079,-0.65) 4(1.079,-0.65) 5(1.079,0) 6(1.079,0.65)
  rect 1.143x1.194 smd: 7(0,0.285)
  rect 0.66x0.356 smd: 8(0,-0.775)
SW2_SPST_3P5X6P0_5P0
  rect 1.6x2.007 smd: 1(0,-2.7) 2(0,2.7)
TP_TH_063
  round 2.311 hole 1.6: 1(0,0)
TPAD_030
  round 0.762 smd: 1(0,0)
TSSOP8
  rect 1.778x0.356 smd: 1(-2.819,0.975) 2(-2.819,0.325) 3(-2.819,-0.325) 4(-2.819,-0.975) 5(2.819,-0.975) 6(2.819,-0.325) 7(2.819,0.325) 8(2.819,0.975)
unnamed#2
  round 1.524 smd: (0,0)
WLCSP4_0P4_0P8X0P8_SMDP
  round 0.254 smd: A1(-0.2,0.2) A2(0.2,0.2) B1(-0.2,-0.2) B2(0.2,-0.2)
XTAL_4_7X5
  rect 2.21x1.397 smd: 1(-3.1,-1.25) 2(3.1,-1.25) 3(3.1,1.25) 4(-3.1,1.25)
XTLOSC4_5X3MM_SM
  rect 1.854x1.397 smd: 1(-1.95,-1.2) 2(1.95,-1.2) 3(1.95,1.2) 4(-1.95,1.2)

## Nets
3V3: C50.1 C51.1 C52.1 C53.1 C56.1 C57.1 C65.1 C66.1 C67.1 C68.1 C70.1 C71.1 J15.1(A1) R23.2 R26.1 R30.1 R36.2 R37.2 R38.2 R39.2 R48.2 R55.1 R58.1 R59.1 R60.1 R62.1 R67.2 U5.7(VDDA/VREFH) U5.15(VDD) U6.8(VCC) U8.13(VDDD) U8.14(VDDA) U9.13(VDDD) U9.14(VDDA) U52.A2(VOUT) U53.A2(VOUT)
3V3_LDO: C75.1 R65.1 U51.2(VOUT) U51.4(TAB) U52.A1(VIN)
5V: J5.A1(5V_2) J5.B1(5V_1) J5.C1(5V_4) J5.D1(5V_3)
24V: C19.1 C20.1 C21.1 C22.1 C24.1 C25.1 C26.1 C27.1 D12.C J18.2 J19.2 J20.2 J21.2 R21.1 R40.1 R41.1 R42.1 R43.1 U8.22(VCC) U9.22(VCC)
P3V3_KL25Z: C9.1 C10.1 C11.1 C12.1 C13.1 C14.1 C17.1 C18.1 J53.1(A1) R19.2 R34.1 R52.1 R53.2 TP89.1(PIN1) U50.1(VDD1) U50.5(VOUT33) U50.9(VDDA) U50.22(VDD2)
P5V0_USB_CONN_VBUS: F50.1 J52.1(P1) TP16.1(PIN1)
P5V_USB: C60.1 C61.1 L50.2 TP77.1(PIN1) U50.6(VREGIN) U51.3(VIN)
VDDA: J5.A46(VDDA)
VSSA: J5.A45(VSSA)
BOOT_MCU: C7.1 R30.2 SW6.1(COMMON) TP11.1(PIN1) U5.14(PTA4/N\M\I\/I2C1_SDA/TPM0_CH1)
CLK_MASTER: U8.43(XTAL1) U9.12(CLK)
CONV_CLK: J7.6(B3) U50.46(PTD5/ADC0_SE6B/SPI1_SCK/UART2_T)
CONV_CS0: J8.6(B3) R50.2 R51.2
CONV_INT: J13.6(B3) U50.42(PTD1/ADC0_SE5B/SPI0_SCK/TPM0_CH)
CONV_MISO: J6.6(B3) U50.48(PTD7/SPI1_MISO/UART0_TX/SPI1_MO)
CONV_MOSI: J14.6(B3) U50.47(PTD6/LLWU_P15/ADC0_SE7B/SPI1_MO)
EE_ADDR0: R54.1 R55.2 U6.1(A0)
EE_ADDR1: R57.1 R58.2 U6.2(A1)
EE_ADDR2: R61.1 R62.2 U6.3(A2)
EEPROM_SCL: J16.2 R33.2 U5.20(PTB0/LLWU_P5/ADC0_SE8/I2C0_SCL/)
EEPROM_SDA: J16.1 R35.2 U5.21(PTB1/ADC0_SE9/I2C0_SDA/TPM1_CH1)
KL25Z_BOOT_ACTIVATE: C54.1 R52.2 SW7.1(COMMON) U50.27(PTB0/LLWU_P5/ADC0_SE8/TSI0_CH0/)
MS1_CQ1: D10.A D11.C J11.2 J12.3 U9.33(CQ1)
MS1_CQ2: D19.A D20.C J23.2 J25.3 U9.28(CQ2)
MS1_GATE1: R25.2 TP15.1(PIN1) U9.38(GATE1)
MS1_GATE2: R44.2 TP18.1(PIN1) U9.37(GATE2)
MS1_INTX: JP8.6 U5.11(PTA1/LPUART0_RX/TPM2_CH0) U9.6(INTX)
MS1_LM1: C5.2 C6.2 C7.2 C8.2 C9.2 C10.2 C11.2 C12.2 C13.2 C14.2 C15.1 C16.2 C17.2 C18.2 C23.2 C24.2 C25.2 C26.2 C27.2 C28.2 C29.2 C30.2 C50.2 C51.2 C52.2 C53.2 C54.2 C55.2 C56.2 C57.2 C58.2 C59.2 C60.2 C61.2 C65.2 C66.2 C67.2 C68.2 C70.2 C71.2 C75.2 D5.C(CATHODE) D6.C(CATHODE) D7.C(CATHODE) D8.A D11.A D17.A D20.A D50.A(ANODE) J5.A2(GND_9) J5.A5(GND_10) J5.A6(GND_11) J5.A26(GND_12) J5.A31(GND_13) J5.A49(GND_14) J5.A65(GND_15) J5.A81(GND_16) J5.B2(GND_1) J5.B5(GND_2) J5.B6(GND_3) J5.B26(GND_4) J5.B31(GND_5) J5.B49(GND_6) J5.B65(GND_7) J5.B81(GND_8) J5.C2(GND_25) J5.C5(GND_26) J5.C6(GND_27) J5.C26(GND_28) J5.C31(GND_29) J5.C49(GND_30) J5.C65(GND_31) J5.C81(GND_32) J5.D2(GND_17) J5.D5(GND_18) J5.D6(GND_19) J5.D26(GND_20) J5.D31(GND_21) J5.D49(GND_22) J5.D65(GND_23) J5.D81(GND_24) J9.4 J9.5 J10.3 J11.3 J12.4 J12.5 J15.3(A2) J15.5(A3) J16.3 J17.2 J17.3 J22.4 J22.5 J23.3 J24.3 J25.4 J25.5 J52.5(P5) J53.3(A2) J53.5(A3) JP5.1 JP6.1 JP7.1 JP8.1 JP9.1 JP10.1 JP11.1 L51.2 Q50.2(EMITTER) R32.2 R47.1 R49.1 R54.2 R57.2 R61.2 SW5.2(NO) SW6.2(NO) SW7.2(NO) SW8.2(NO) TP13.1(PIN1) TP82.1(PIN1) U5.8(VREFL/VSSA) U5.16(VSS) U5.33(EP_PAD) U6.4(GND) U7.3(COM_ANODE) U8.15(GND) U8.30(LM2) U8.31(LM1) U8.39(LGND) U8.47(TP1) U8.49(EPAD) U9.15(GND) U9.30(LM2) U9.31(LM1) U9.39(LGND) U9.47(TP1) U9.49(EPAD) U50.2(VSS1) U50.11(VREFL) U50.12(VSSA) U50.23(VSS2) U50.49(EX_PAD) U51.1(GND) U52.B2(GND) U53.B2(GND) Y5.2 Y5.4 Y50.2(GND1) Y50.4(GND2)
MS1_LP1: C6.1 D10.C J11.1 J12.2 Q5.4(SOURCE1) Q5.8(SOURCE2) R28.1 U9.35(LP1)
MS1_LP2: C28.1 D19.C J23.1 J25.2 Q7.4(SOURCE1) Q7.8(SOURCE2) R45.1 U9.26(LP2)
MS1_MISO: JP8.2 U5.28(PTC7/CMP0_IN1/SPI0_MISO/SPI0_MO) U9.10(MISO)
MS1_MOSI: JP8.3 U5.27(PTC6/LLWU_P10/CMP0_IN0/SPI0_MOS) U9.9(MOSI)
MS1_RXD1: JP10.9 U9.1(RXD1/CYCT1)
MS1_RXD2: JP10.5 U9.16(RXD2/CYCT2)
MS1_SCLK: JP8.4 U5.26(PTC5/LLWU_P9/SPI0_SCK/LPTMR0_AL) U9.8(SCLK)
MS1_SDX1: JP10.6 U5.1(PTE0/CLKOUT32K/SPI1_MISO/LPUART) U9.4(SDX1)
MS1_SDX2: JP10.2 U5.2(PTE1/SPI1_MOSI/LPUART1_RX/SPI1_) U9.19(SDX2)
MS1_SEN1: C22.2 J21.1 Q5.1(DRAIN1) Q5.2(DRAIN2) Q5.5(DRAIN3) Q5.6(DRAIN4) Q5.7(DRAIN5) R28.2 R43.2 U9.23(SEN1)
MS1_SEN2: C21.2 J20.1 Q7.1(DRAIN1) Q7.2(DRAIN2) Q7.5(DRAIN3) Q7.6(DRAIN4) Q7.7(DRAIN5) R42.2 R45.2 U9.24(SEN2)
MS1_SSX: JP8.5 U5.25(PTC4/LLWU_P8/SPI0_PCS0/LPUART1_) U9.7(SSX)
MS1_SSX1: TP9.1(PIN1) U5.24(PTC3/LLWU_P7/SPI1_SCK/LPUART1_R)
MS1_TEMP: TP21.1(PIN1) U9.46(TEMP)
MS1_TXD1: JP10.7 U9.2(TXD1/SYNC1)
MS1_TXD2: JP10.3 U9.17(TXD2/SYNC2)
MS1_TXEN1: JP10.8 U9.3(TXEN1)
MS1_TXEN2: JP10.4 U9.18(TXEN2)
MS2_CQ1: D8.C D9.A J9.3 J10.2 U8.33(CQ1)
MS2_CQ2: D17.C D18.A J22.3 J24.2 U8.28(CQ2)
MS2_GATE1: R31.2 TP14.1(PIN1) U8.38(GATE1)
MS2_GATE2: R68.2 TP17.1(PIN1) U8.37(GATE2)
MS2_INTX: JP7.6 U5.12(PTA2/LPUART0_TX/TPM2_CH1) U8.6(INTX)
MS2_LP1: C8.1 D9.C J9.2 J10.1 Q6.4(SOURCE1) Q6.8(SOURCE2) R29.1 U8.35(LP1)
MS2_LP2: C30.1 D18.C J22.2 J24.1 Q8.4(SOURCE1) Q8.8(SOURCE2) R46.1 U8.26(LP2)
MS2_MISO: JP7.2 U5.32(PTD7/SPI1_MISO/LPUART0_TX/2C1_S) U8.10(MISO)
MS2_MOSI: JP7.3 U5.31(PTD6/LLWU_P15/ADC0_SE7B/SPI1_MO) U8.9(MOSI)
MS2_RXD1: JP9.9 U8.1(RXD1/CYCT1)
MS2_RXD2: JP9.5 U8.16(RXD2/CYCT2)
MS2_SCLK: JP7.4 U5.30(PTD5/ADC0_SE6B/SPI1_SCK/UART2_T) U8.8(SCLK)
MS2_SDX1: JP9.6 U5.22(PTC1/LLWU_P6/RTC_CLKIN/ADC0_SE1) U8.4(SDX1)
MS2_SDX2: JP9.2 U5.23(PTC2/ADC0_SE11/I2C1_SDA/TPM0_CH) U8.19(SDX2)
MS2_SEN1: C20.2 J19.1 Q6.1(DRAIN1) Q6.2(DRAIN2) Q6.5(DRAIN3) Q6.6(DRAIN4) Q6.7(DRAIN5) R29.2 R41.2 U8.23(SEN1)
MS2_SEN2: C19.2 J18.1 Q8.1(DRAIN1) Q8.2(DRAIN2) Q8.5(DRAIN3) Q8.6(DRAIN4) Q8.7(DRAIN5) R40.2 R46.2 U8.24(SEN2)
MS2_SSX: JP7.5 U5.29(PTD4/LLWU_P14/SPI1_PCS0/UART2_R) U8.7(SSX)
MS2_TEMP: TP20.1(PIN1) U8.46(TEMP)
MS2_TXD1: JP9.7 U8.2(TXD1/SYNC1)
MS2_TXD2: JP9.3 U8.17(TXD2/SYNC2)
MS2_TXEN1: JP9.8 U8.3(TXEN1)
MS2_TXEN2: JP9.4 U8.18(TXEN2)
RST_KL25Z: C16.1 J53.10(B5) R34.2 SW8.1(COMMON) TP12.1(PIN1) U50.26(PTA20/R\E\S\E\T\)
RST_MCU: C5.1 J15.10(B5) R26.2 SW5.1(COMMON) TP8.1(PIN1) U5.19(PTA20/R\E\S\E\T\)
SHIELD_K20USB: J52.S1(SHLD1) J52.S2(SHLD2) J52.S3(SHLD3) J52.S4(SHLD4) L51.1
SPI0_CLK: J5.B48(SPI0_CLK) R14.2
SPI0_CS0: J5.B46(S\P\I\0\_\C\S\0\) R20.2
SPI0_CS1: J5.B47(S\P\I\0\_\C\S\1\) R16.2
SPI0_MISO: J5.B44(SPI0_MISO/IO1) R13.2
SPI0_MOSI: J5.B45(SPI0_MOSI/IO0) R17.2
SPI1_CLK: J5.B7(SDHC_CLK/SPI1_CLK) J7.4(B2)
SPI1_CS0: J5.B9(SDHC_D3/S\P\I\1\_\C\S\0\) J8.4(B2)
SPI1_CS1: J5.B8(SDHC_D3/S\P\I\1\_\C\S\1\) R18.2
SPI1_MISO: J5.B11(SDHC_D0/SPI1_MISO) J6.4(B2)
SPI1_MOSI: J5.B10(SDHC_CMD/SPI1_MOSI) J14.4(B2)
SPI2_CLK: J5.D7(SPI2_CLK) R15.2
SPI2_CS0: J5.D9(S\P\I\2\_\C\S\0\) R24.2
SPI2_CS1: J5.D8(S\P\I\2\_\C\S\1\) R22.2
SPI2_MISO: J5.D11(SPI2_MISO) R12.2
SPI2_MOSI: J5.D10(SPI2_MOSI) R27.2
SWD_CLK: J15.4(B2) U5.10(PTA0/SWD_CLK/TPM0_CH5)
SWD_CLK_KL25Z: J53.4(B2) U50.17(PTA0/SWD_CLK/TSI0_CH1/TPM0_CH5)
SWD_DIO: J15.2(B1) U5.13(PTA3/SWD_DIO/I2C1_SCL/TPM0_CH0)
SWD_DIO_KL25Z: J53.2(B1) U50.20(PTA3/SWD_DIO/TSI0_CH4/I2C1_SCL/)
TC_USB_ID_TP: J52.4(P4) TP90.1(PIN1)
TWR_3V3: J5.A3(3.3V_4) J5.A4(3.3V_5) J5.A36(3.3V_6) J5.A82(3.3V_7) J5.B3(3.3V_1) J5.B36(3.3V_2) J5.B82(3.3V_3) J5.C3(3.3V_11) J5.C4(3.3V_12) J5.C36(3.3V_13) J5.C82(3.3V_14) J5.D3(3.3V_8) J5.D36(3.3V_9) J5.D82(3.3V_10) R66.1 U53.A1(VIN) U53.B1(EN)
TWR_CLK: J7.1(A1) J7.3(A2) J7.5(A3) JP6.5 U5.4(PTE17/ADC0_DM1/ADC0_SE5A/SPI0_S)
TWR_CS0: J8.1(A1) J8.3(A2) J8.5(A3) JP6.6 U5.3(PTE16/ADC0_DP1/ADC0_SE1/SPI0_PC)
TWR_INT: J13.1(A1) J13.3(A2) J13.5(A3) JP6.2 U5.9(PTE30/ADC0_SE23/CMP0_IN4/TPM0_C)
TWR_INT_1: R7.2 R8.1
TWR_INT_2: J13.4(B2) R9.1
TWR_INT_3: R6.2 R10.1
TWR_INT_4: R5.2 R11.1
TWR_MISO: J6.1(A1) J6.3(A2) J6.5(A3) JP6.3 U5.6(PTE19/ADC0_DM2/ADC0_SE6A/SPI0_M)
TWR_MOSI: J14.1(A1) J14.3(A2) J14.5(A3) JP6.4 U5.5(PTE18/ADC0_DP2/ADC0_SE2/SPI0_MO)
USB_CONN_DN: J52.2(P2) R64.1 U7.1(CATHODE1)
USB_CONN_DP: J52.3(P3) R63.1 U7.2(CATHODE2)
USB_DM: R64.2 U50.4(USB0_DM)
USB_DP: R63.2 U50.3(USB0_DP)
VREFH: C15.2 C55.1 R53.1 TP80.1(PIN1) U50.10(VREFH)
N51941022: R35.1 R60.2 U6.5(SDA)
N51941025: R33.1 R59.2 U6.6(SCL)
N51968614: D15.C(CATHODE) U9.41(LED1)
N51968623: D16.C(CATHODE) U9.40(LED2)
N51972698: C29.1 U9.44(XTAL2) Y5.3
N51980032: R32.1 U6.7(WP)
N51981285: D7.A(ANODE) R23.1
N51981437: D6.A(ANODE) R21.2
N51981716: D16.A(ANODE) R39.1
N51981719: D15.A(ANODE) R38.1
N51986239: R49.2 R67.1 U9.48(CLK_EN)
N52006957: J8.2(B1) R16.1 R18.1 R20.1 R22.1 R24.1
N52007703: J5.B60(IRQ_C) R9.2
N52007706: J5.B62(IRQ_A) R8.2
N52011483: R47.2 R48.1 U8.48(CLK_EN)
N52011777: D13.C(CATHODE) U8.41(LED1)
N52011781: D14.C(CATHODE) U8.40(LED2)
N52011843: D14.A(ANODE) R37.1
N52011845: D13.A(ANODE) R36.1
N52039256: J5.B56(IRQ_G) R11.2
N52039259: J5.B58(IRQ_E) R10.2
N52039370: J13.2(B1) R5.1 R6.1 R7.1
N52105751: Q50.3(COLLECTOR) R65.2 U52.B1(EN)
N52105774: Q50.1(BASE) R66.2
N52116188: C23.1 U9.43(XTAL1) Y5.1
N52149421: J25.1 TP22.1(PIN1)
N52149434: J12.1 TP10.1(PIN1)
N52149447: J22.1 TP19.1(PIN1)
N52149460: J9.1 TP5.1(PIN1)
N52159106: Q6.3(GATE1) R31.1
N52159127: Q8.3(GATE1) R68.1
N52159490: D12.A J17.1(PIN)
N52178619: Q7.3(GATE1) R44.1
N52178906: Q5.3(GATE1) R25.1
N52281250: J6.2(B1) R12.1 R13.1
N52284736: D50.C(CATHODE) F50.2 L50.1
N52285941: C59.1 R56.1 U50.24(PTA18/EXTAL0/UART1_RX/TPM_CLKIN) Y50.1
N52286024: C58.1 R56.2 U50.25(PTA19/XTAL0/UART1_TX/TPM_CLKIN1) Y50.3
N52286041: R51.1 U50.44(PTD3/SPI0_MISO/UART2_TX/TPM0_CH)
N52290882: TP83.1(PIN1) U50.13(PTE29/CMP0_IN5/ADC0_SE4B/TPM0_C)
N52290920: TP78.1(PIN1) U50.28(PTB1/ADC0_SE9/TSI0_CH6/I2C0_SDA)
N52290933: TP76.1(PIN1) U50.29(PTB2/ADC0_SE12/TSI0_CH7/I2C0_SC)
N52290949: TP75.1(PIN1) U50.30(PTB3/ADC0_SE13/TSI0_CH8/I2C0_SD)
N52290962: TP74.1(PIN1) U50.31(PTB16/TSI0_CH9/SPI1_MOSI/UART0_)
N52290975: TP73.1(PIN1) U50.32(PTB17/TSI0_CH10/SPI1_MISO/UART0)
N52291034: TP72.1(PIN1) U50.33(PTC0/ADC0_SE14/TSI0_CH13/EXTRG_)
N52291047: TP67.1(PIN1) U50.34(PTC1/LLWU_P6/RTC_CLKIN/ADC0_SE1)
N52291060: TP71.1(PIN1) U50.35(PTC2/ADC0_SE11/TSI0_CH15/I2C1_S)
N52291085: TP66.1(PIN1) U50.36(PTC3/LLWU_P7/UART1_RX/TPM0_CH2/)
N52291099: TP70.1(PIN1) U50.37(PTC4/LLWU_P8/SPI0_PCS0/UART1_TX)
N52291114: TP64.1(PIN1) U50.38(PTC5/LLWU_P9/SPI0_SCK/LPTMR0_AL)
N52291127: TP69.1(PIN1) U50.39(PTC6/LLWU_P10/CMP0_IN0/SPI0_MOS)
N52291143: TP58.1(PIN1) U50.40(PTC7/CMP0_IN1/SPI0_MISO/SPI0_MO)
N52291156: TP84.1(PIN1) U50.15(PTE24/TPM0_CH0/I2C0_SCL)
N52291179: TP68.1(PIN1) U50.41(PTD0/SPI0_PCS0/TPM0_CH0)
N52291192: TP57.1(PIN1) U50.43(PTD2/SPI0_MOSI/UART2_RX/TPM0_CH)
N52291212: R50.1 U50.45(PTD4/LLWU_P14/SPI1_PCS0/UART2_R)
N52302946: TP6.1(PIN1) U5.17(PTA18/EXTAL0/LPUART1_RX/TPM_CLK)
N52302949: TP7.1(PIN1) U5.18(PTA19/XTAL0/LPUART1_TX/TPM_CLKI)
N52312996: J14.2(B1) R17.1 R27.1
N52313183: J7.2(B1) R14.1 R15.1
N52316776: D5.A(ANODE) R19.1
N522864580: TP79.1(PIN1) U50.7(PTE20/ADC0_DP0/ADC0_SE0/TPM1_CH)
N522864581: TP81.1(PIN1) U50.8(PTE21/ADC0_DM0/ADC0_SE4A/TPM1_C)
N522864582: TP87.1(PIN1) U50.14(PTE30/DAC0_OUT/ADC0_SE23/CMP0_I)
N5228645815: TP85.1(PIN1) U50.18(PTA1/TSI0_CH2/UART0_RX/TPM2_CH0)
N5228645818: TP86.1(PIN1) U50.21(PTA4/N\M\I\/TSI0_CH5/I2C1_SDA/T)
N5228645847: TP88.1(PIN1) U50.16(PTE25/TPM0_CH1/I2C0_SDA)

Pads without a net: J5 A7 A8 A9 A10 A11 A12 A13 A14 A15 A16 A17 A18 A19 A20 A21 A22 A23 A24 A25 A27 A28 A29 A30 A32 A33 A34 A35 A37 A38 A39 A40 A41 A42 A43 A44 A47 A48 A50 A51 A52 A53 A54 A55 A56 A57 A58 A59 A60 A61 A62 A63 A64 A66 A67 A68 A69 A70 A71 A72 A73 A74 A75 A76 A77 A78 A79 A80 B4 B12 B13 B14 B15 B16 B17 B18 B19 B20 B21 B22 B23 B24 B25 B27 B28 B29 B30 B32 B33 B34 B35 B37 B38 B39 B40 B41 B42 B43 B50 B51 B52 B53 B54 B55 B57 B59 B61 B63 B64 B66 B67 B68 B69 B70 B71 B72 B73 B74 B75 B76 B77 B78 B79 B80 C7 C8 C9 C10 C11 C12 C13 C14 C15 C16 C17 C18 C19 C20 C21 C22 C23 C24 C25 C27 C28 C29 C30 C32 C33 C34 C35 C37 C38 C39 C40 C41 C42 C43 C44 C45 C46 C47 C48 C50 C51 C52 C53 C54 C55 C56 C57 C58 C59 C60 C61 C62 C63 C64 C66 C67 C68 C69 C70 C71 C72 C73 C74 C75 C76 C77 C78 C79 C80 D4 D12 D13 D14 D15 D16 D17 D18 D19 D20 D21 D22 D23 D24 D25 D27 D28 D29 D30 D32 D33 D34 D35 D37 D38 D39 D40 D41 D42 D43 D44 D45 D46 D47 D48 D50 D51 D52 D53 D54 D55 D56 D57 D58 D59 D60 D61 D62 D63 D64 D66 D67 D68 D69 D70 D71 D72 D73 D74 D75 D76 D77 D78 D79 D80; J15 6 7 8 9; J53 6 7 8 9; U8 5 11 12 20 21 25 27 29 32 34 36 42 44 45; U9 5 11 20 21 25 27 29 32 34 36 42 45; U50 19

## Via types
v1: diameter 0.457, hole 0.203, TOP to BOTTOM, 335 vias
v2: diameter 0.457, hole 0.206, TOP to BOTTOM, 52 vias

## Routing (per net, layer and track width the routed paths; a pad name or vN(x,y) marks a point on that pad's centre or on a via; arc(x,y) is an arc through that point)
3V3: length 38.4
  TOP w0.254: U8.13 v1(62.28,25.74) ; v1(45.67,63.89) 45.41,63.63 U5.15 ; U8.14 v1(60.66,26.24) ; U9.13 v1(37.82,25.66) ; U5.7 49.56,61.98 v1(49.82,61.72) ; U9.14 v1(36.2,26.16)
  TOP w0.33: U6.8 v1(27.91,45.81)
  TOP w0.508: R38.2 v1(27.18,40.91) ; v1(53.54,40.98) R37.2 R36.2 ; R67.2 v1(31.18,20.5) ; R30.1 v1(41.17,54.76) ; R26.1 v1(62.43,59.12) ; R39.2 v1(29.08,40.91) ; R48.2 v1(55.64,20.57) ; R23.2 v1(71.54,65.94)
  L2_PWR w0.381: 65.05,50.14 J15.1 66.14,50.83
  BOTTOM w0.254: U52.A2 v1(72.54,16.51) ; v1(60.66,26.24) 60.6,26.29 C65.1 ; U53.A2 v1(73.18,12.73) ; v1(37.82,25.66) 37.83,25.65 C68.1 ; v1(62.28,25.74) 62.29,25.73 C67.1 ; C66.1 v1(36.2,26.16)
  BOTTOM w0.432: C53.1 v1(49.82,61.72) C52.1 ; R60.1 R59.1 29.67,45.34 29.2,45.81 v1(27.91,45.81) 27.32,45.21 C56.1 C57.1 ; C50.1 v1(45.67,63.89) C51.1
  BOTTOM w0.508: R55.1 R58.1 R62.1 v1(18.62,42.74) ; v1(62.28,25.74) 61.92,25.37 C70.1 60.66,25.91 v1(60.66,26.24) ; v1(37.82,25.66) 37.46,25.3 C71.1 36.2,25.83 v1(36.2,26.16)
3V3_LDO: length 13.1
  BOTTOM w0.254: R65.1 74.12,16.97 U52.A1
  BOTTOM w0.864: C75.1 75.83,19.7 U51.4 74.12,18.78 R65.1
  BOTTOM w1.168: U51.2 U51.4
5V: length 163.2
  TOP w0.508: J5.D1 3.51,3.6 3.51,5.94 v1(3.68,6.12) ; J5.B1 86.44,76.97 v1(86.44,74.57)
  L3_INT_1 w0.508: v1(3.68,6.12) 3.89,6.32 3.89,11.71 1.8,13.8 1.8,65.91 11.38,75.49 11.46,75.51 65.78,75.51 70.26,71.03 73.29,71.03 74.57,69.75 76.12,69.75 78.56,72.19 84.05,72.19 v1(86.44,74.57)
  BOTTOM w0.508: v1(3.68,6.12) 3.68,5.94 3.5,5.75 J5.C1 ; v1(86.44,74.57) 86.44,76.6 J5.A1
24V: length 46.2
  TOP w0.254: v1(62.28,30.24) 62.28,30.24 U8.22 ; U9.22 37.42,30.16 37.51,30.08 38.41,30.08 C25.1
  TOP w0.508: R41.1 v1(69.04,36.09) ; R41.1 v1(68.12,37.39) ; R41.1 v1(68.12,34.8) ; C22.1 v1(42.37,34.49) ; R40.1 v1(57.81,36.09) ; R40.1 v1(58.72,34.8) ; R40.1 58.72,37.13 58.72,37.14 v1(58.72,37.44) ; v1(44.15,37.36) 43.66,36.88 R43.1 ; R21.1 v1(71.54,67.84) ; C27.1 v1(42.67,33.2) ; C27.1 v1(43.87,31.01) ; C27.1 v1(41.48,31.01) ; R42.1 v1(34.26,34.72) ; R42.1 v1(34.26,37.31) ; R42.1 v1(33.35,36.02) ; R43.1 v1(43.66,34.72) ; R43.1 v1(44.58,36.02) ; C25.1 v1(38.99,30.66) ; C26.1 v1(66.07,31.12) ; C26.1 v1(67.26,33.3) ; C26.1 v1(68.45,31.12) ; C24.1 62.29,30.23 v1(62.28,30.24) ; C20.1 v1(66.81,34.57) ; C21.1 v1(35.57,34.49) ; C19.1 v1(60.03,34.57)
  BOTTOM w0.381: 67.61,37.69 J19.2 ; J19.2 68.56,38.63 ; J19.2 67.61,39.57 ; J19.2 66.67,38.63 ; 42.21,38.56 J21.2 ; J21.2 43.15,37.62 ; J21.2 44.09,38.56 ; J21.2 43.15,39.5 ; J18.2 60.17,38.63 ; J18.2 58.29,38.63 ; J18.2 59.23,37.69 ; J18.2 59.23,39.57 ; J20.2 35.71,38.56 ; J20.2 33.83,38.56 ; J20.2 34.77,39.5 ; J20.2 34.77,37.62
  vias: v1(64.59,45.62) v1(64.61,44.35) v1(64.59,43.21) v1(65.48,46.41) v1(65.48,42.29) v1(66.88,46.41) v1(67.01,42.29) v1(67.94,45.62) v1(67.94,44.35) v1(67.94,43.21)
P3V3_KL25Z: length 56.8
  TOP w0.457: v1(54.5,49.56) 54.5,50.5 C10.1 ; v1(53.36,47.65) 53.23,47.78 C13.1 ; C18.1 47.77,45.62 v1(47.01,44.86) ; v1(53.19,51.8) 52.56,51.8 C9.1 C11.1 C12.1 ; C17.1 46.76,45.11 v1(47.01,44.86) ; v1(45.53,43.97) R34.1 47.01,44.48 v1(47.01,44.86) ; C14.1 52.35,45.87 v1(52.6,45.62)
  TOP w0.508: v1(71.74,69.7) 70.94,69.7 R19.2
  TOP w0.61: C14.1 C13.1
  L2_PWR w0.381: 48.54,40.97 J53.1 49.63,40.29
  L4_INT_2 w0.508: v1(71.74,69.7) 66.37,64.33 66.37,50.45 65.55,49.63 61.16,49.63 59.81,50.98 55.93,50.98 v1(54.5,49.56)
  BOTTOM w0.254: U50.22 47.17,45.01 v1(47.01,44.86) ; U50.9 53.21,47.8 v1(53.36,47.65) ; U50.5 52.84,49.8 53,49.63 53.12,49.63 53.16,49.59 53.19,49.59 v1(53.22,49.56) ; U50.1 v1(53.19,51.8)
  BOTTOM w0.457: R53.2 v1(56.16,46.25)
  BOTTOM w0.508: TP89.1 48.28,40.54 J53.1 ; R52.1 41.25,48.64 v1(40.6,48.64)
P5V0_USB_CONN_VBUS: length 6.7
  BOTTOM w0.508: TP16.1 10.91,35.78 F50.1 9.96,38.68 J52.1
P5V_USB: length 91.8
  TOP w0.508: v1(56.41,50.32) 56.41,49.18 57.17,48.41 58.44,48.41 60.09,46.76 60.09,42.83 62.63,40.29 68.22,40.29 69.39,39.12 69.39,37.51 76.83,30.07 v1(76.83,27.61)
  L4_INT_2 w0.508: v1(56.41,50.32) 56.41,48.92 54.63,47.14 54.63,45.75 52.09,43.21 51.13,43.21 49.12,41.2 46.48,41.2 46.2,40.92 v1(45.61,40.92)
  BOTTOM w0.254: U50.6 52.74,49.3 52.98,49.06 53.43,49.06 54,49.62 54,49.94 TP77.1
  BOTTOM w0.508: v1(56.41,50.32) 56.41,50.7 55.9,51.21 TP77.1 ; U51.3 75.5,26.29 v1(76.83,27.61) C61.1 ; L50.2 16.94,39.39 C60.1 17.71,40.16 31.64,40.16 32.41,40.92 v1(45.61,40.92)
BOOT_MCU: length 27.8
  TOP w0.127: TP11.1 SW6.1 38.12,50.83 40.03,52.73 42.15,52.73 43.07,53.66 R30.2 C7.1 45.11,55.02 45.23,54.89 v1(45.74,54.89) ; U5.14 45.91,63.43 46,63.52 46,63.59 46.11,63.71 46.11,64.28 46.37,64.54 v1(46.39,64.54)
  L3_INT_1 w0.127: v1(45.74,54.89) 46.88,54.89 48.7,56.71 48.7,63.86 47.96,64.61 46.45,64.61 v1(46.39,64.54)
CLK_MASTER: length 20.5
  TOP w0.127: U8.43 v1(53.86,28.24) ; v1(37.77,24.66) 37.42,25.01 U9.12
  BOTTOM w0.127: v1(53.86,28.24) 53.86,27.29 51.23,24.66 v1(37.77,24.66)
CONV_CLK: length 29.6
  L4_INT_2 w0.127: v1(52.6,54.13) 52.35,54.38 45.23,54.38 43.58,52.73 37.23,52.73 35.71,54.26 35.71,59.84 J7.6
  BOTTOM w0.127: U50.46 50.67,53.1 51.7,54.13 v1(52.6,54.13)
CONV_CS0: length 15.9
  BOTTOM w0.127: R50.2 R51.2 50.31,57.18 49.04,57.18 48.21,58.01 41.73,58.01 39.8,59.94 J8.6
CONV_INT: length 23.2
  L4_INT_2 w0.127: v1(48.92,53.21) 47.48,51.78 29.04,51.78 J13.6
  BOTTOM w0.127: U50.42 48.66,52.45 48.66,52.96 v1(48.92,53.21)
CONV_MISO: length 34.7
  L4_INT_2 w0.127: J6.6 28.76,60.8 28.76,54.09 30.79,52.06 46.21,52.06 47.9,53.75 50.82,53.75 51.84,52.73 v1(52.47,52.73)
  BOTTOM w0.127: U50.48 52.19,52.45 v1(52.47,52.73)
CONV_MOSI: length 20.9
  L4_INT_2 w0.127: v1(51.96,53.62) 51.56,54.03 46.53,54.03 44.95,52.45 35.86,52.45 35.2,53.11 J14.6
  BOTTOM w0.127: v1(51.96,53.62) 51.58,53.62 51.17,53.2 U50.47
EE_ADDR0: length 4.8
  TOP w0.127: U6.1 22.11,45.81 v1(21.16,46.76)
  BOTTOM w0.127: R55.2 v1(21.16,46.76) R54.1
EE_ADDR1: length 4.5
  TOP w0.127: U6.2 21.24,45.16 v1(21.16,45.24)
  BOTTOM w0.127: R57.1 v1(21.16,45.24) R58.2
EE_ADDR2: length 4.8
  TOP w0.127: v1(21.16,43.71) 21.95,44.51 U6.3
  BOTTOM w0.127: R62.2 v1(21.16,43.71) R61.1
EEPROM_SCL: length 24.3
  TOP w0.127: v1(43.38,60.73) 43.63,60.98 U5.20 ; R33.2 33.15,44.5 33.68,45.03 J16.2
  L3_INT_1 w0.127: J16.2 35.65,46.01 35.65,51.92 36.37,52.65 36.37,56.25 40.97,60.85 43.27,60.85 v1(43.38,60.73)
EEPROM_SDA: length 26.2
  TOP w0.127: v1(42.88,60.29) 43.57,60.29 43.76,60.48 U5.21 ; R35.2 33.15,43.05 33.71,42.49 J16.1
  L3_INT_1 w0.127: J16.1 35.93,43.75 35.93,51.81 37.26,53.14 37.26,56.2 41.63,60.57 42.6,60.57 v1(42.88,60.29)
KL25Z_BOOT_ACTIVATE: length 18.8
  TOP w0.127: SW7.1 v1(30.96,49)
  BOTTOM w0.127: v1(30.96,49) 31.77,49.81 39.65,49.81 40.15,50.32 42.46,50.32 42.97,49.81 C54.1 R52.2 42.97,48.03 43.71,47.3 U50.27
MS1_CQ1: length 42.7
  TOP w0.254: U9.33 v1(32.36,32.62)
  TOP w0.508: J12.3 J11.2 9.81,57.56 10.6,56.77 10.6,56.58 11.53,55.65 D10.A D11.C v1(16.66,53.62)
  L3_INT_1 w0.508: v1(32.36,32.62) 31.7,33.28 30.64,33.28 18.82,45.11 18.82,51.46 v1(16.66,53.62)
MS1_CQ2: length 38.7
  TOP w0.254: U9.28 v1(34.86,32.62)
  TOP w0.508: v1(15.89,18.83) D20.C D19.A 11.63,20.98 10.69,21.92 10.69,22.14 9.81,23.02 J23.2 J25.3
  L4_INT_2 w0.508: v1(15.89,18.83) 18.22,18.83 31.03,31.63 33.87,31.63 v1(34.86,32.62)
MS1_GATE1: length 39
  TOP w0.127: U9.38 29.62,30.66 29.59,30.7 29.59,33.8 TP15.1 30.99,41.07 v1(29.26,42.8) ; R25.2 v1(21.37,63.65)
  L3_INT_1 w0.127: v1(29.26,42.8) 29.26,47.24 v1(23.39,53.11)
  BOTTOM w0.127: v1(23.39,53.11) 21.74,54.76 21.74,58.7 21.37,59.06 v1(21.37,63.65)
MS1_GATE2: length 13.3
  TOP w0.127: R44.2 v1(21.37,29.11) ; TP18.1 30.35,32.36 30.21,32.21 v1(30.21,31.78) U9.37
  BOTTOM w0.127: v1(30.21,31.78) 27.54,29.11 v1(21.37,29.11)
MS1_INTX: length 58.2
  TOP w0.127: U9.6 v1(33.36,24.2) ; v1(47.65,64.16) 47.41,63.93 U5.11
  L3_INT_1 w0.127: v1(47.65,64.16) 47.65,64.13 46.32,62.8 45.92,62.8 43.83,60.71 43.83,60.55 43.12,59.84 42.69,59.84 42.25,60.29 41.75,60.29 38.72,57.26 38.72,53.77 38.75,53.74 38.75,50.06 38.21,49.52 38.21,48.15 38.29,48.07 38.29,33.77 35.47,30.95 35.47,26.34 33.36,24.22 v1(33.36,24.2) 33.36,22.05 31.36,20.05 31.05,20.05 JP8.6
